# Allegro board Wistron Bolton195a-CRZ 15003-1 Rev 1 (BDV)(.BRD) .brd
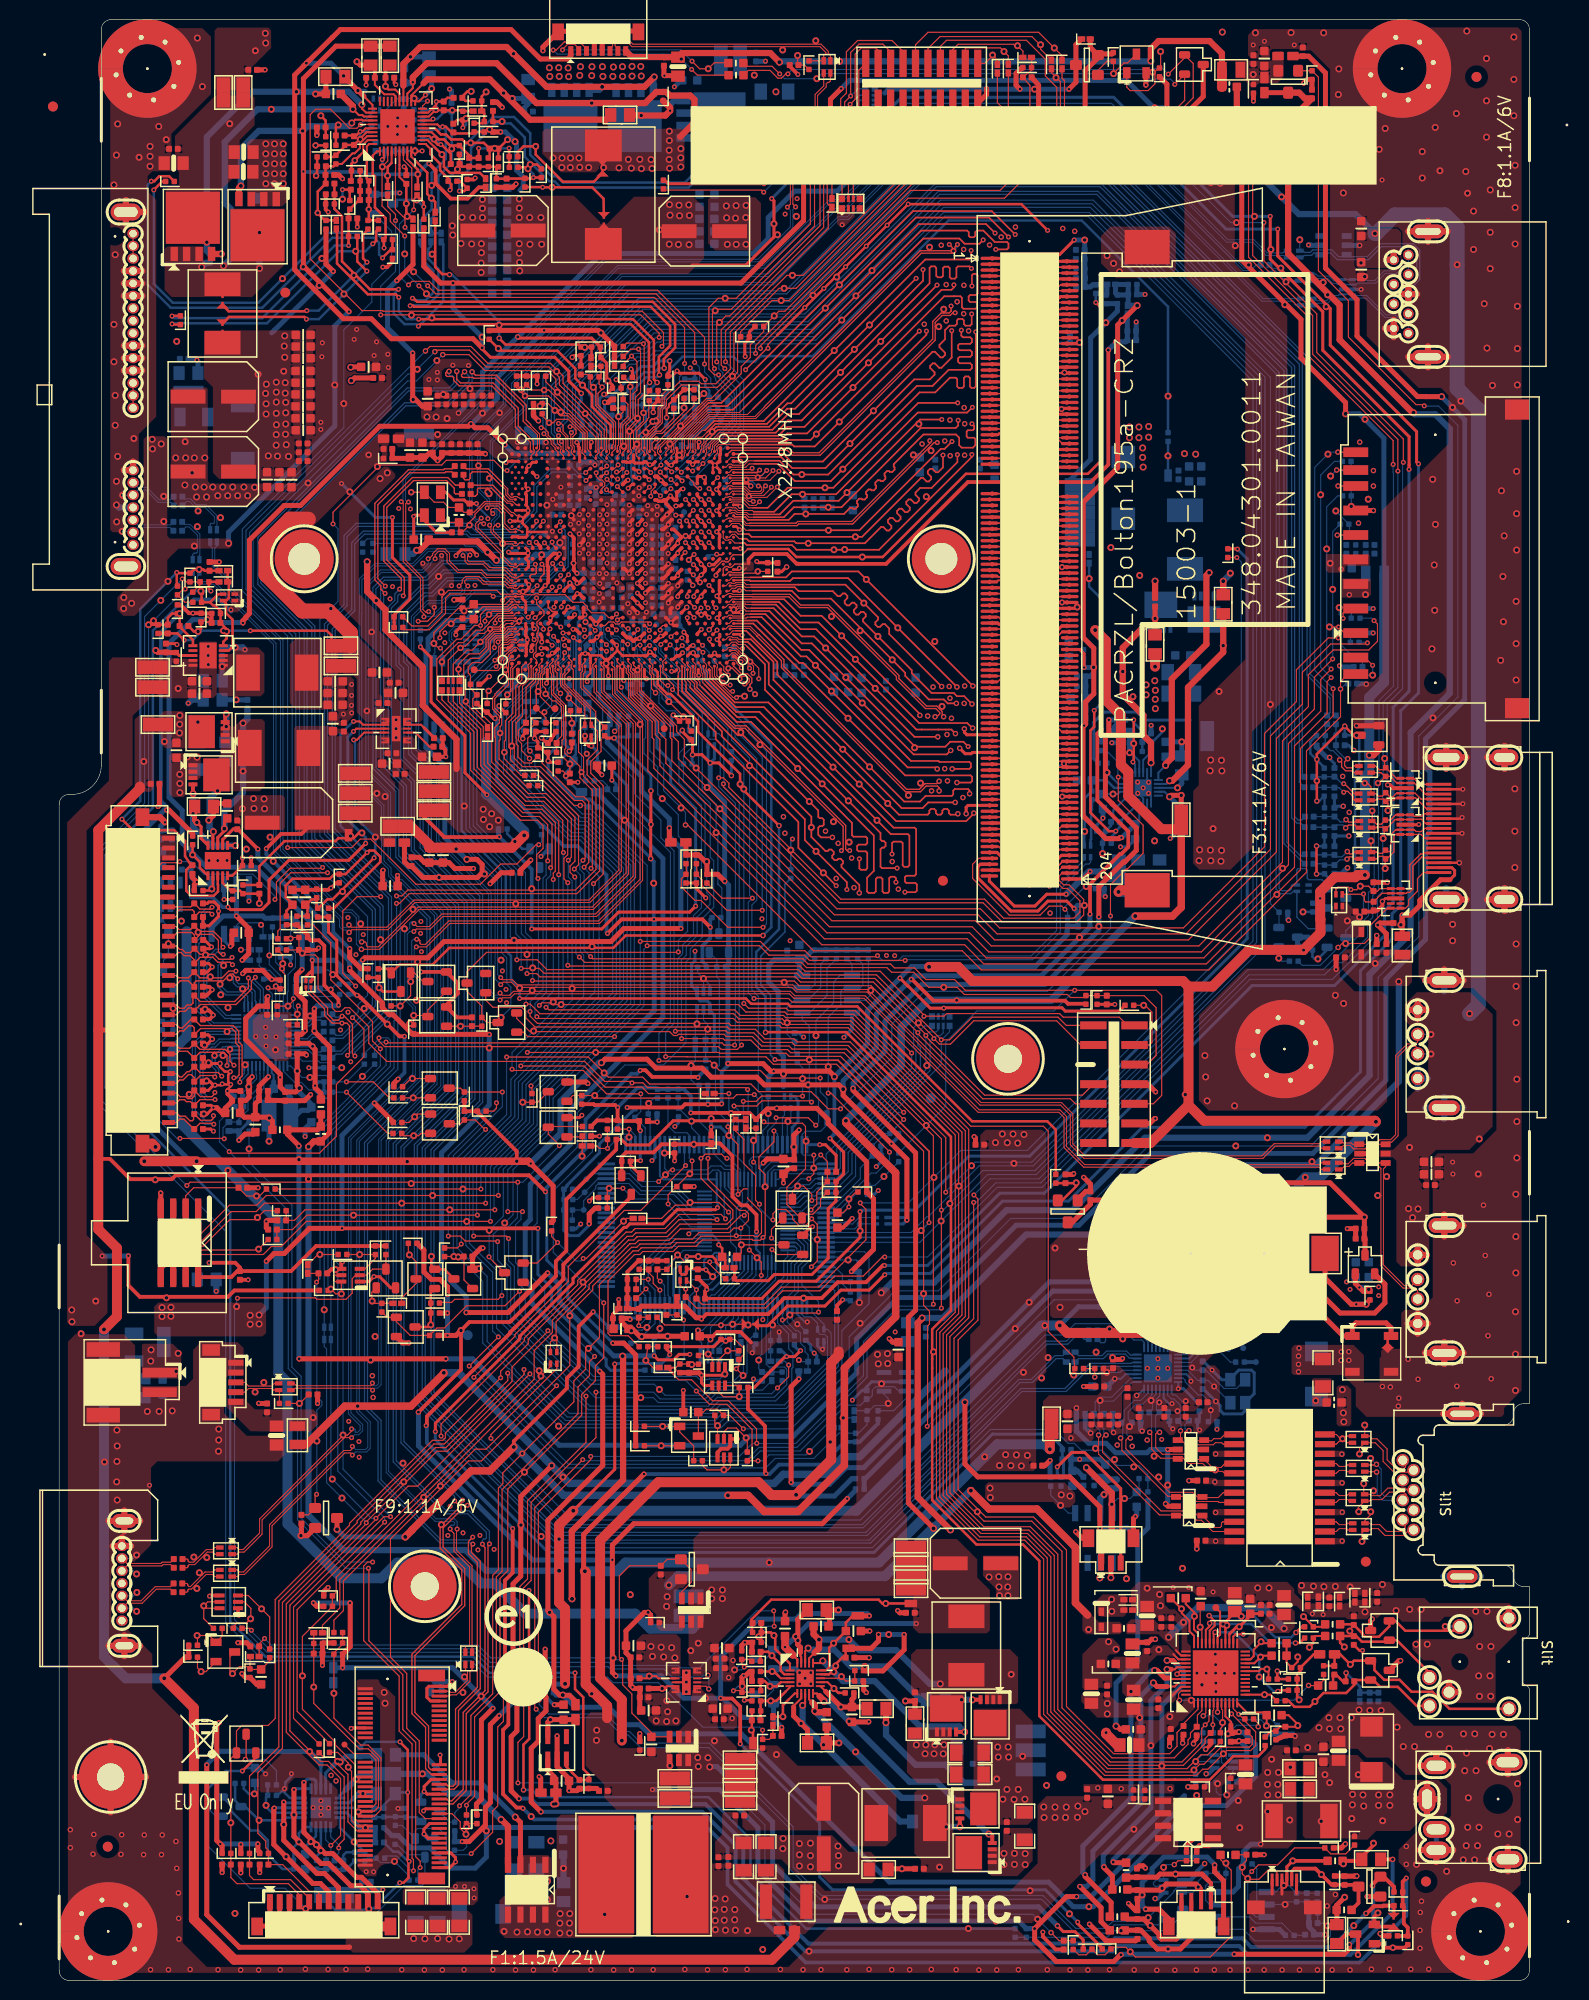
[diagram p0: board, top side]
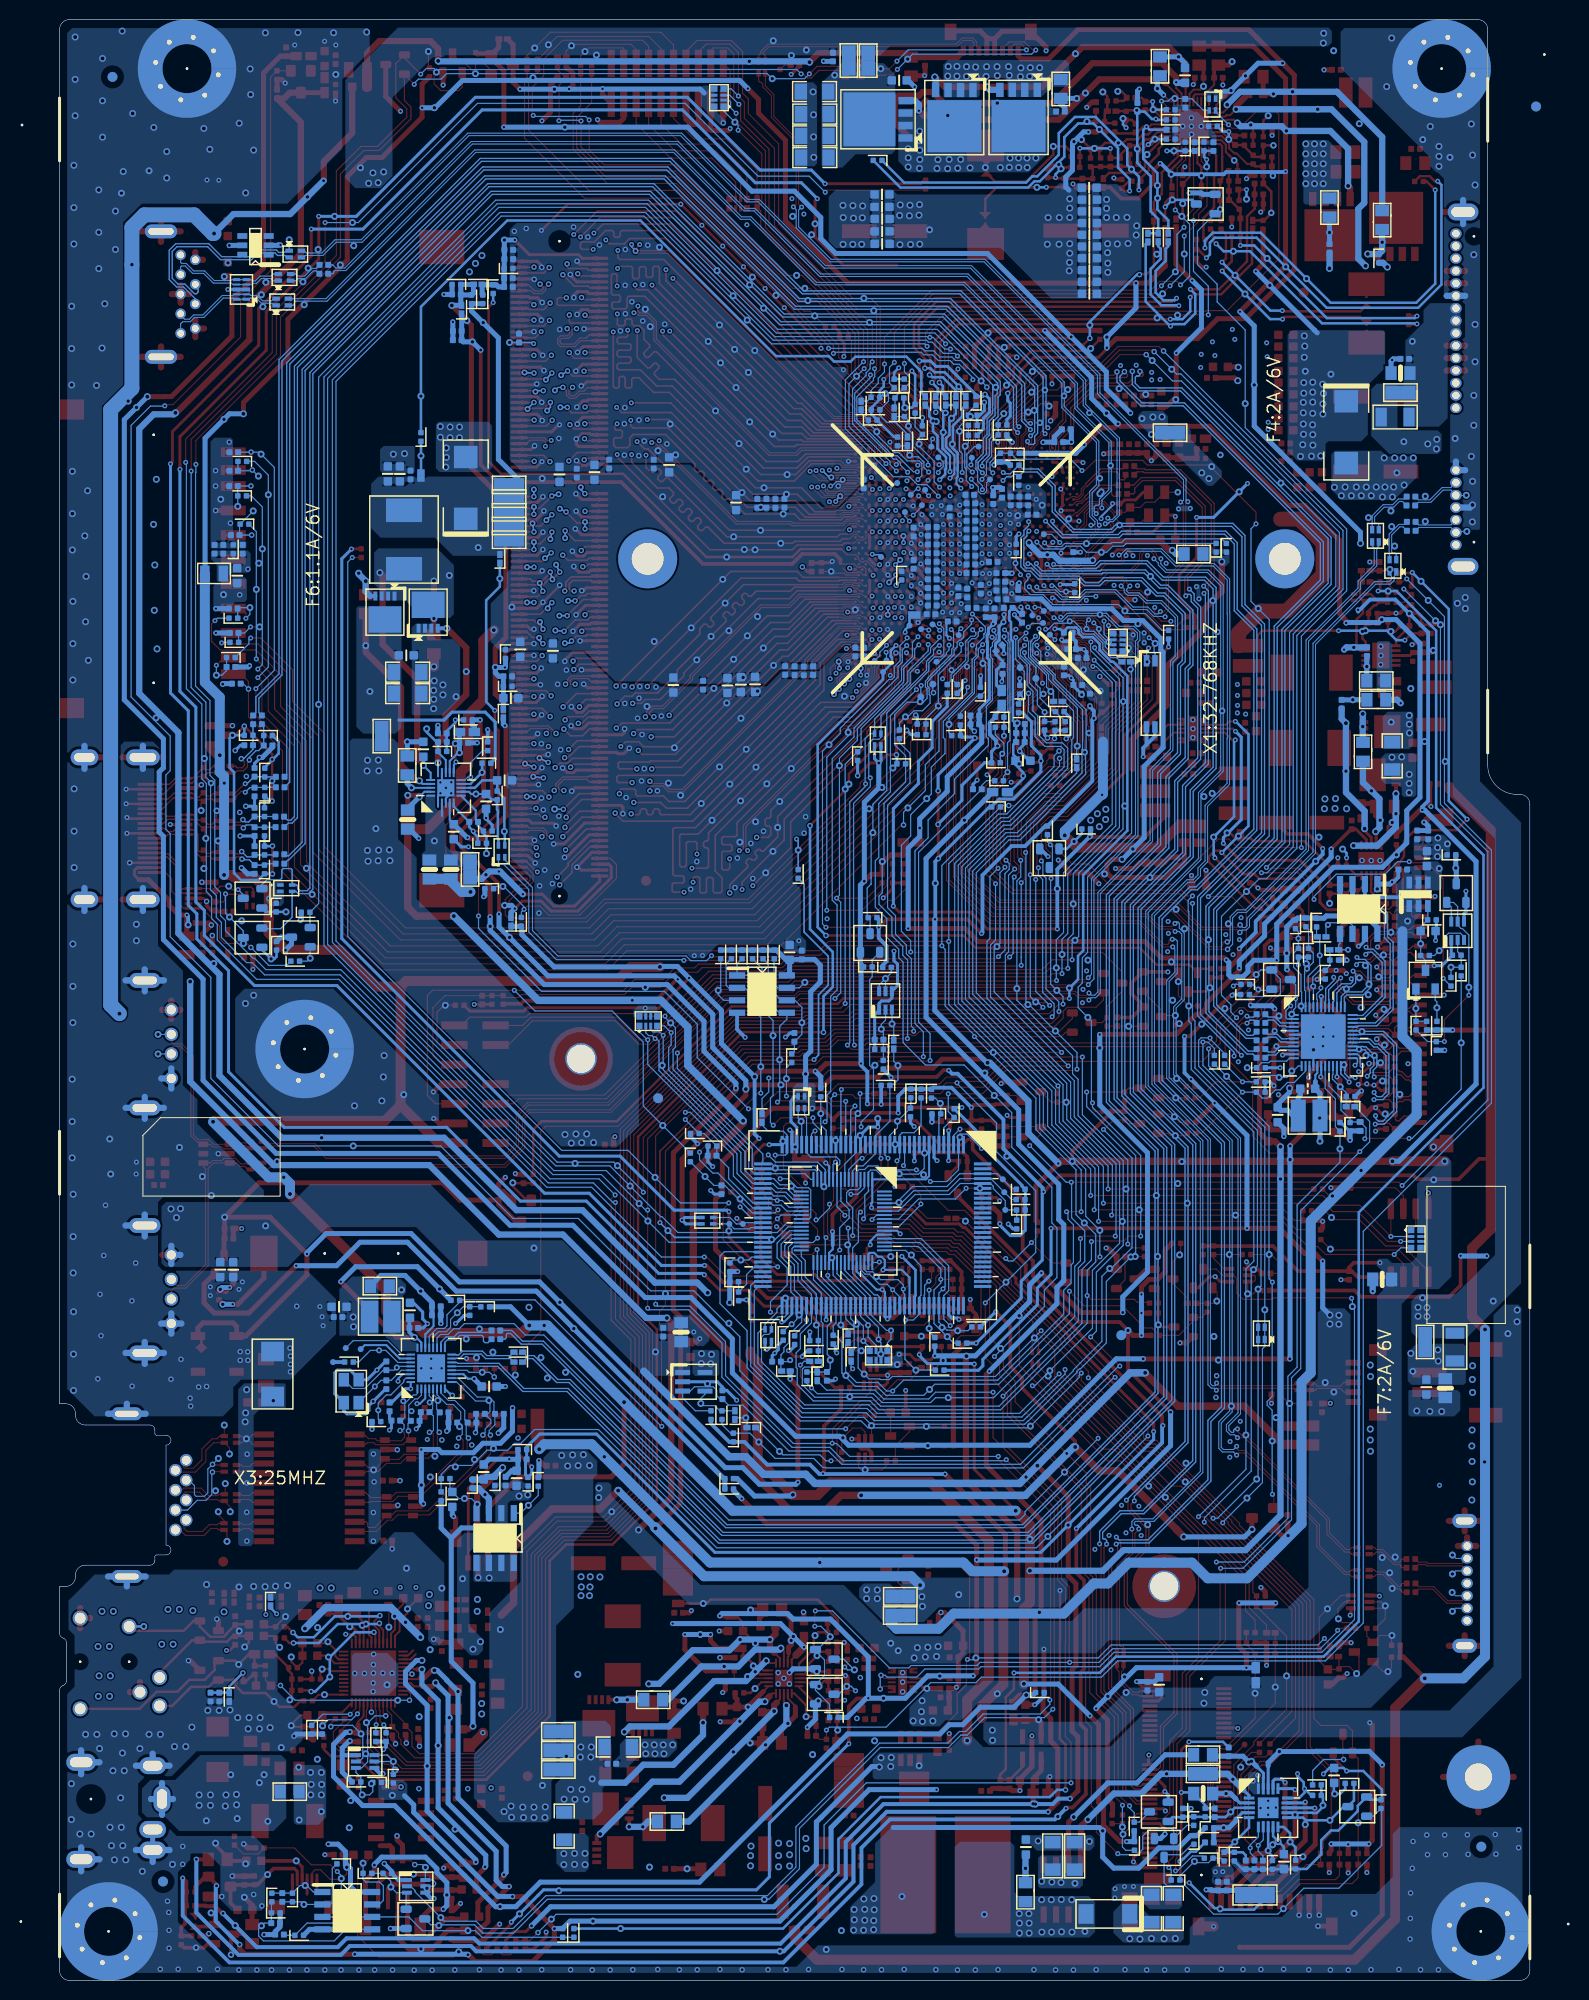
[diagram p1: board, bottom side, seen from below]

Outline 150 x 200 mm; copper layers: TOP, L2VCC, L3, BOTTOM. Coordinates in mm from the lower left corner of the outline.
Outline path: 0,119.97 0,1 arc(0.29,0.29) 1,0 149,0 arc(149.71,0.29) 150,1 150,29.6 arc(149.9,29.9) 149.65,30.08 arc(149.4,30.26) 149.3,30.55 149.3,34.45 arc(149.4,34.74) 149.65,34.92 arc(149.9,35.1) 150,35.4 150,40.18 149.38,40.18 arc(148.67,40.47) 148.38,41.18 148.38,41.35 arc(148.09,42.06) 147.38,42.35 140.78,42.35 arc(140.43,42.5) 140.28,42.85 140.28,43.2 arc(140.22,43.34) 140.08,43.4 139.14,43.4 arc(138.64,43.9) 139.14,44.4 139.14,54.6 arc(138.64,55.1) 139.14,55.6 140.08,55.6 arc(140.22,55.66) 140.28,55.8 140.28,56.15 arc(140.43,56.5) 140.78,56.65 147.38,56.65 arc(148.09,56.94) 148.38,57.65 148.38,57.82 arc(148.67,58.53) 149.38,58.82 150,58.82 150,199 arc(149.71,199.71) 149,200 5.3,200 arc(4.59,199.71) 4.3,199 4.3,123.97 arc(3.42,121.85) 1.3,120.97 1,120.97 arc(0.29,120.68) 0,119.97

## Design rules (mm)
constraint set DEFAULT: min track width 0.127, pair gap 0.102
net group C_GPP_TXN0: nets C_GPP_TXN0 PCIE_C_TXN0
net group C_GPP_TXN1: nets C_GPP_TXN1 PCIE_C_TXN1
net group C_GPP_TXP0: nets C_GPP_TXP0 PCIE_C_TXP0
net group C_GPP_TXP1: nets C_GPP_TXP1 PCIE_C_TXP1
net group CK_BLAN_DN: nets CK_BLAN_DN F_GPP_CLK0N
net group CK_BLAN_DP: nets CK_BLAN_DP F_GPP_CLK0P
net group DP0_AUXN: nets DP0_AUXN DP0_AUXN_PS8625
net group DP0_AUXP: nets DP0_AUXP DP0_AUXP_PS8625
net group DP0_TXN0: nets DP0_TXN0 M_DP0_TXN0
net group DP0_TXN1: nets DP0_TXN1 M_DP0_TXN1
net group DP0_TXP0: nets DP0_TXP0 M_DP0_TXP0
net group DP0_TXP1: nets DP0_TXP1 M_DP0_TXP1
net group DP1_TX: nets DP1_AUXN DP1_AUXP
net group F_USB0N: nets F_USB0N USB_PN0_C
net group F_USB0P: nets F_USB0P USB_PP0_C
net group F_USB1N: nets F_USB1N USB_PN1_2-
net group F_USB1P: nets F_USB1P USB_PP1_2+
net group F_USB2N: nets F_USB2N USB_PN2_11-
net group F_USB2P: nets F_USB2P USB_PP2_11+
net group F_USB4N: nets F_USB4N USB_PN4_C
net group F_USB4P: nets F_USB4P USB_PP4_C
net group F_USB5N: nets F_USB5N USB_PN5*
net group F_USB5P: nets F_USB5P USB_PP5*
net group HDMI_4: nets HDMI_HPDET_CN HDMI_HTPLG_CN1
net group MEM_MA_DQS0: nets MEM_MA_DQS_N0 MEM_MA_DQS_P0
net group MEM_MA_DQS1: nets MEM_MA_DQS_N1 MEM_MA_DQS_P1
net group MEM_MA_DQS2: nets MEM_MA_DQS_N2 MEM_MA_DQS_P2
net group MEM_MA_DQS3: nets MEM_MA_DQS_N3 MEM_MA_DQS_P3
net group MEM_MA_DQS4: nets MEM_MA_DQS_N4 MEM_MA_DQS_P4
net group MEM_MA_DQS5: nets MEM_MA_DQS_N5 MEM_MA_DQS_P5
net group MEM_MA_DQS6: nets MEM_MA_DQS_N6 MEM_MA_DQS_P6
net group MEM_MA_DQS7: nets MEM_MA_DQS_N7 MEM_MA_DQS_P7
net group OTHER_10_VIA_14: nets 12V_EN_G 12V_EN_G1
net group PCIE_C_RXN0: nets PCIE_C_RXN0 PCIE_RXN_LAN_C
net group PCIE_C_RXP0: nets PCIE_C_RXP0 PCIE_RXP_LAN_C
net group SATA_RXN1_C: nets SATA_RXN1_C SATA_RXN1_N
net group SATA_RXP1_C: nets SATA_RXP1_C SATA_RXP1_N
net group SATA_TXN1_C: nets SATA_TXN1_C SATA_TXN1_N
net group SATA_TXP1_C: nets SATA_TXP1_C SATA_TXP1_N
net group SCALAR_4: nets EDID_RDY RTL_ISOLATE_N
net group USB30_RN0_C: nets USB30_RN0_C USB30_RXN0
net group USB30_RP0_C: nets USB30_RP0_C USB30_RXP0
net group AMPGND_40: nets AMPGND
net group AUDIO_8_10: nets AUD_CBN AUD_CBP BZ_ON
net group AUDIO_12_10: nets AUD_VREF
net group AUDIO_AMP: nets F_HPO_L F_HPO_L_1 F_HPO_R F_HPO_R_1 FM_L_CODEC FM_R_CODEC HP_OUT_L_CON HP_OUT_R_CON JDREF_1 MIC2 MIC_IN_JACK MIC_VREFL MIC_VREFR PCH_SPKR1
net group AZALIA-MW: nets AZ_BCLK AZ_BCLK_M AZ_RST_N AZ_RST_N_M AZ_SDIN0 AZ_SDIN0_R AZ_SDIN1 AZ_SDIN2 AZ_SDIN3 AZ_SDOUT AZ_SDOUT_M AZ_SYNC AZ_SYNC_M
net group CR-DATA: nets SD_CD# SD_CLK SD_CMD SD_DATA0 SD_DATA1 SD_DATA2 SD_DATA3 SD_WP
net group DMIC_5.5-MW: nets DMIC_CLK DMIC_CLK_W DMIC_DATA DMIC_DATA_W
net group DP1_C_TXN0: nets DP1_C_TXN0 DP1_TXN0 DP1_TXN0_C
net group DP1_C_TXN1: nets DP1_C_TXN1 DP1_TXN1 DP1_TXN1_C
net group DP1_C_TXN2: nets DP1_C_TXN2 DP1_TXN2 DP1_TXN2_C
net group DP1_C_TXN3: nets DP1_C_TXN3 DP1_TXN3 DP1_TXN3_C
net group DP1_C_TXP0: nets DP1_C_TXP0 DP1_TXP0 DP1_TXP0_C
net group DP1_C_TXP1: nets DP1_C_TXP1 DP1_TXP1 DP1_TXP1_C
net group DP1_C_TXP2: nets DP1_C_TXP2 DP1_TXP2 DP1_TXP2_C
net group DP1_C_TXP3: nets DP1_C_TXP3 DP1_TXP3 DP1_TXP3_C
net group EDP_LVDS: nets EDP_LVDS_L0_N EDP_LVDS_L0_P EDP_LVDS_L1_N EDP_LVDS_L1_P EDP_LVDS_L2_N EDP_LVDS_L2_P EDP_LVDS_L3_N EDP_LVDS_L3_P EDP_LVDS_LC_N EDP_LVDS_LC_P EDP_LVDS_U0_N EDP_LVDS_U0_P EDP_LVDS_U1_N EDP_LVDS_U1_P EDP_LVDS_U2_N EDP_LVDS_U2_P EDP_LVDS_U3_N EDP_LVDS_U3_P EDP_LVDS_UC_N EDP_LVDS_UC_P
net group EUP_CTRL_4: nets EUP_EN EUP_R1 EUP_R2 EUP_R3 EUP_R4 EUP_R5 EUP_R6
net group FAN: nets CPU_FANCTL1 SIO_BLEN SIO_BLEN_SMI
net group HDA_4: nets AUD_LINK_RST_N1 COMBO JACK JD_HP_R PD PD#_C
net group HDA_4_COMBO: nets COMBO
net group HDT: nets APU_DBRDY APU_DBREQ APU_DBREQ# APU_TCK APU_TDI APU_TDO APU_TMS APU_TRST HDT_C_M1 HDT_C_M2 HDT_C_M3 HDT_PW_M3 HDT_PW_M4 HDT_RST0 HDT_RST1 HDT_TRST
net group INT_SPKR_20_20: nets SPKR_L+ SPKR_L- SPKR_OUT_L+_C SPKR_OUT_L-_C SPKR_OUT_R+_C SPKR_OUT_R-_C SPKR_R+ SPKR_R-
net group LAN_CTRL_4: nets LAN_CLKREQ_N LAN_EEDO LAN_EESK LAN_RSET
net group LCD_CTRL_4_VIA_14: nets LCD_5V_EN LCD_5V_EN1 LCD_5V_EN2 LCD_5V_EN3 LCD_5V_EN4 SCALAR_VDD_EN1
net group LED_15_10: nets LINK*_ACTIVITY_L PWRLED_CON SPEED_100*_L SUSLED_1 SUSLED_2 SUSLED_CON SUSLED_CON_P1 SUSLED_N SUSLED_R_N_1 SUSLED_R_N_PWM V_5_LED
net group LVDS-4: nets BKLT_ADJ BKLT_EN BKLT_EN_D DP0_HPD_G DP_BLON DP_DIGON DP_VARY_BL DP_VARY_BL_R PS8625_BKLT_EN PS8625_BKLT_PWM PS8625_LCD_PW_EN
net group MDI0+: nets MDI0+ MDI0+_C MDI0+_R
net group MDI0-: nets MDI0- MDI0-_C MDI0-_R
net group MDI1+: nets MDI1+ MDI1+_C MDI1+_R
net group MDI1-: nets MDI1- MDI1-_C MDI1-_R
net group MDI2+: nets MDI2+ MDI2+_C MDI2+_R
net group MDI2-: nets MDI2- MDI2-_C MDI2-_R
net group MDI3+: nets MDI3+ MDI3+_C MDI3+_R
net group MDI3-: nets MDI3- MDI3-_C MDI3-_R
net group MEM_DA_CHECK_DM-MW: nets MEM_MA_DM8
net group MEM_MA_CTL_CLK: nets MEM_MA0_CKE0 MEM_MA0_CKE1 MEM_MA0_CLK0_N MEM_MA0_CLK0_P MEM_MA0_CLK1_N MEM_MA0_CLK1_P MEM_MA0_CS_L0 MEM_MA0_CS_L1 MEM_MA0_ODT0 MEM_MA0_ODT1 MEM_MA_ADD0 MEM_MA_ADD1 MEM_MA_ADD2 MEM_MA_ADD3 MEM_MA_ADD4 MEM_MA_ADD5 MEM_MA_ADD6 MEM_MA_ADD7 MEM_MA_ADD8 MEM_MA_ADD9 MEM_MA_ADD10 MEM_MA_ADD11 MEM_MA_ADD12 MEM_MA_ADD13 MEM_MA_ADD14 MEM_MA_ADD15 MEM_MA_BANK0 MEM_MA_BANK1 MEM_MA_BANK2 MEM_MA_CAS# MEM_MA_RAS# MEM_MA_WE#
net group MEM_MA_DQ0: nets MEM_MA_DATA0 MEM_MA_DATA1 MEM_MA_DATA2 MEM_MA_DATA3 MEM_MA_DATA4 MEM_MA_DATA5 MEM_MA_DATA6 MEM_MA_DATA7 MEM_MA_DM0
net group MEM_MA_DQ1: nets MEM_MA_DATA8 MEM_MA_DATA9 MEM_MA_DATA10 MEM_MA_DATA11 MEM_MA_DATA12 MEM_MA_DATA13 MEM_MA_DATA14 MEM_MA_DATA15 MEM_MA_DM1
net group MEM_MA_DQ2: nets MEM_MA_DATA16 MEM_MA_DATA17 MEM_MA_DATA18 MEM_MA_DATA19 MEM_MA_DATA20 MEM_MA_DATA21 MEM_MA_DATA22 MEM_MA_DATA23 MEM_MA_DM2
net group MEM_MA_DQ3: nets MEM_MA_DATA24 MEM_MA_DATA25 MEM_MA_DATA26 MEM_MA_DATA27 MEM_MA_DATA28 MEM_MA_DATA29 MEM_MA_DATA30 MEM_MA_DATA31 MEM_MA_DM3
net group MEM_MA_DQ4: nets MEM_MA_DATA32 MEM_MA_DATA33 MEM_MA_DATA34 MEM_MA_DATA35 MEM_MA_DATA36 MEM_MA_DATA37 MEM_MA_DATA38 MEM_MA_DATA39 MEM_MA_DM4
net group MEM_MA_DQ5: nets MEM_MA_DATA40 MEM_MA_DATA41 MEM_MA_DATA42 MEM_MA_DATA43 MEM_MA_DATA44 MEM_MA_DATA45 MEM_MA_DATA46 MEM_MA_DATA47 MEM_MA_DM5
net group MEM_MA_DQ6: nets MEM_MA_DATA48 MEM_MA_DATA49 MEM_MA_DATA50 MEM_MA_DATA51 MEM_MA_DATA52 MEM_MA_DATA53 MEM_MA_DATA54 MEM_MA_DATA55 MEM_MA_DM6
net group MEM_MA_DQ7: nets MEM_MA_DATA56 MEM_MA_DATA57 MEM_MA_DATA58 MEM_MA_DATA59 MEM_MA_DATA60 MEM_MA_DATA61 MEM_MA_DATA62 MEM_MA_DATA63 MEM_MA_DM7
net group MEM_MISC-MW: nets MEM_MA_EVENT_L MEM_MA_RESET# SIO_MEM_EVENT_L
net group OCP_6: nets ADP_OCP OCP_0 OCP_1 OCP_2 OCP_3 OCP_6 OCP_7 OCP_8
net group OTHER_4: nets 1D5V_S3_PG 1D5V_S3_PG_R A_RST_N APU_BLEN_SMI APU_PROCHOT# APU_PROCHOT#_R APU_PWRGD APU_PWRGD_BUF APU_SIC APU_SID APU_SVC APU_SVD APU_SVT AUD_CPVEE BLANCLK_REQ_N BLINK BT_DISABLE_N# BUFFER1_M4 BYPASSCLK_H BYPASSCLK_L DAC_ZVSS DIMM1_SA0 DP0_HPD_N DP0_HPD_NR DP1_HPD_N DP_2K_ZVSS DP_150_ZVSS DP_REXT EC_SMI# EC_SMI#_APU EUP_DSW_SEL FP_RST_N HDMI_EN ICH_RSMRST_N_R ITE_DEB KA20GATE KA20GATE_SIO KBRST_N LAD0_FWH0 LAD1_FWH1 LAD2_FWH2 LAD3_FWH3 LAN_WAKE LDT_PWRGD_R LDT_RST LDT_RST#_BUF LDT_RST#_R LFRAMEJ_FW4 LPC_CLK0_R LPC_CLK1 LPC_CLK1_R LPC_PME_N LPC_SIO_CLK0 MEM_ZVDDIO MODE_CFG0 MODE_CFG1 NGFF_SUSCLK P_RX_ZVDD P_TX_ZVDD PB_IN_N_1 PCIE_RST_N PCIE_RST_N_R PCIE_WAKE_N_PCIE PCIRST2# PLT_WLAN_RST PLT_WLAN_RST# PLTRST_LAN PME#_M PWRBTN# PWRBTN#_1 PWRBTN_IN PWRGD_3V_LL PWRGD_PS_L PWRGD_PS_L1 PWRGD_PS_L2 RSMRST*_R RSMRST_N RSMRST_N_FCH SERIRQ_N SIO_PWNBTN_N SLP_S3_N SLP_S5_N SLP_S5_N_R SPI_SW SVC_VDD SVD_VDD SVT_VDD SW_ON_N_SIO SYS_ID2 SYS_ID3 SYS_PWRGD TEST18_M TEST19_M TEST_MODE THERMAL_SHUT# THERMAL_SHUT#_SIO USB_COMP_M USB_OC_01 USB_OC_02 USB_OC_03 USB_OC_23 USBSS_CALRN USBSS_CALRP V_3P3_DBP VRM_PWRGD VSS_BEEMA WLAN_CLKREQ WLAN_CLKREQ_CPU#
net group OTHER_4_VIA_14: nets SYS_PWRGD_HV SYS_PWRGD_HV_1 SYS_PWRGD_HV_2
net group OTHER_10: nets ADU_LDO_CAP APU_ALERT# HDMI_Q76_M Q5102_GATE Q5103_GATE SPKR
net group OTHER_40: nets CPU_FANTACH1 FAN5V_OUT FAN5V_OUT_CONN
net group POWER_4.5: nets PWR_ID0 PWR_ID1 PWR_ID2
net group POWER_10: nets 0D95V_S0_EN 1D8V_S0_EN APU_VDDIO_AZ M_VREFDQ SENSE_A SIO_MAIN_VCC3 SIO_VREF VCORE_PWROK
net group POWER_10_10: nets 0D95V_S5_PG 0P95V_MAIN_APU_M 1P8V_PWR_PG +1P5V_LPS_APU PWR_1D8V_EN PWR_1D8V_FB PWR_1D8V_FB_A PWR_3D3V_ENTRIP1_D PWR_3D3V_ENTRIP2 PWR_3D3V_ENTRIP2_D PWR_3D3V_FB PWR_3D3V_FB_A PWR_3D3V_LDO3 PWR_5V3V_EMN PWR_5V3V_ENLDO PWR_5V3V_LDO5 PWR_5V3V_PGOOD PWR_5V3V_TON PWR_5V_ENTRIP1 PWR_5V_FB PWR_5V_FB_A PWR_CORE_PH1N PWR_CORE_PH1P PWR_CPU_COMP PWR_CPU_COMP_A PWR_CPU_COMPNB PWR_CPU_COMPNB_A PWR_CPU_EN PWR_CPU_FB PWR_CPU_FB_A PWR_CPU_FB_B PWR_CPU_FB_C PWR_CPU_FBNB PWR_CPU_FBNB_A PWR_CPU_FBNB_B PWR_CPU_IMON PWR_CPU_ISEN1 PWR_CPU_ISEN2 PWR_CPU_ISUMN PWR_CPU_ISUMN_A PWR_CPU_ISUMNNB PWR_CPU_ISUMNNB_B PWR_CPU_ISUMP_A PWR_CPU_NB_IMON PWR_CPU_NB_NTC PWR_CPU_NB_NTCA PWR_CPU_NTC PWR_CPU_NTC_A PWR_CPU_PWROK PWR_CPU_RTN PWR_CPU_VDDIO PWR_CPU_VR_HOT PWR_CPU_VSEN PWR_CPU_VSENNB PWR_V1P5A_EN PWR_VDDNB_ISUMP_A PWR_VDDNB_PH_N PWR_VDDNB_PH_P PWR_VDDP_CS PWR_VDDP_EN PWR_VDDP_FB PWR_VDDP_FB_A PWR_VDDP_RF PWR_VDDQ_CS PWR_VDDQ_EN PWR_VDDQ_FB PWR_VDDQ_SENSE PWR_VDDQ_TON PWR_VDDQ_VDD PWR_VDDQ_VTT_EN V_VCORE_EN VBAT_SB_N VDD_095_FB_H_CTL VDDCR_CPU_SENSE VDDCR_NB_SENSE VDDIO_SUS_FB_H VDDIO_SUS_FB_R VDDIO_SUS_SENSE VSS_SENSE
net group POWER_10_10_VIA_14: nets ISET LPF OZ554_EMA OZ554_PWM RT SSTCMP SSTCMP_1 STATUS
net group POWER_20: nets 1D5V_S5 3D3V_2136 3D3V_S5_RSV +3VM +RTCVCC APU_M_VREFDQ_SUS APU_VDD33_ALW APU_VDD_33 BATTERY D2_M D2_M1 DDR_VREF_S3 MEM_VREFCA_SUS P_1.2V_EDP P_3.3V_EDP_VDDIO P_3.3V_EDP_VDDIOX PS8625_SW PWR_1D8V_SVIN PWR_5V3V_VIN PWR_V1P5A PWR_V1P5A_VIN SIO_VCORE VTT_CT_0.95V VTT_CT_1.8V VTT_CT_3.3V VTT_CT_5VC
net group POWER_20_20_VIA_14: nets ISEN1 ISEN2 ISEN3 ISEN4 ISW OZ554_VIN PWR_1D8V_SNB PWR_3D3V_BOOT PWR_3D3V_BOOT_A PWR_3D3V_SNB PWR_5V_BOOT PWR_5V_BOOT_A PWR_5V_SNB PWR_CORE_BOOT1 PWR_CORE_BOOT1_A PWR_CORE_SNB PWR_VDDNB_BOOT PWR_VDDNB_BOOT_A PWR_VDDNB_SNB PWR_VDDP_BOOT PWR_VDDP_BOOT_A PWR_VDDP_SNB PWR_VDDQ_BOOT PWR_VDDQ_BOOT_A PWR_VDDQ_SNB VREF
net group POWER_20_VIA_14: nets V_5_SUS1
net group POWER_25_20_VIA_14: nets LDR LDR_1 PWR_3D3V_HG PWR_3D3V_HG_A PWR_3D3V_LG PWR_5V_HG PWR_5V_HG_A PWR_5V_LG PWR_CORE_HG1 PWR_CORE_HG1_A PWR_CORE_LG1 PWR_VDDNB_HG PWR_VDDNB_HG_A PWR_VDDNB_LG PWR_VDDP_HG PWR_VDDP_HG_A PWR_VDDP_LG PWR_VDDQ_HG PWR_VDDQ_HG_A PWR_VDDQ_LG SNB
net group POWER_40: nets 1D5V_S0 +3VL +5VL PWR_VDDQ_VDDP PWR_VDDQ_VTTIN SIO_AGND SIO_AVCC3
net group POWER_40_VIA_14: nets 5V_S5_LCD_DOWN +5VLCDDDC V_5_PWR1
net group POWER_60: nets 0D75V_S0 PWR_CPU_VDD PWR_CPU_VDDP
net group PS8625: nets PS8625_HPD
net group PWRGD_4_10: nets 3V_5V_POK APU_VRM_PWRGD PWRGD_3V_B_1 PWROK3_1 PWROK3_1_R PWROK3_2 PWROK3_2_R S0_PWR_GOOD SIO_ATXPG V12 V33
net group RUNPWR_4_VIA_14: nets 12V_EN_D RUN_EN RUNPWR_G RUNPWR_R3 RUNPWR_R4 RUNPWR_R5 RUNPWR_R6
net group SATA_RX0N: nets SATA_RX0N SATA_RXN0_C SATA_RXN0_N
net group SATA_RX0P: nets SATA_RX0P SATA_RXP0_C SATA_RXP0_N
net group SATA_TX0N: nets SATA_TX0N SATA_TXN0_C SATA_TXN0_N
net group SATA_TX0P: nets SATA_TX0P SATA_TXP0_C SATA_TXP0_N
net group SD_DATA-MS: nets SD_CLK_CH SD_CMD_CH SD_DATA0_CH_C SD_DATA1_CH_C SD_DATA2_CH_C SD_DATA3_CH_C SD_PWRCTL_CH
net group SIO_4: nets 5V_FANCTL1_FSM# BT_DISABLE_N CPU_FANCTL1_5V DIMM_TMPIN2 EC_EUP EC_EUP_EN EC_EUP_EN# HM_VCCP HM_VCCP_R KBCLK KDAT LDRQ# MCLK MDAT PCIRST1# PLTRST*_SIO REMOTE1+ SIO_3VSB SIO_AMD SVID_EN SIO_BOARD_ID1 SIO_BOARD_ID2 SIO_BOARD_ID3 SIO_CE_N SIO_CLK_DB SIO_COPEN# SIO_DAT_DB SIO_DEBUG_RX SIO_DEBUG_TX SIO_GP31 SIO_GP45 SIO_JP2 SIO_K8PWR_EN SIO_PCIRSTIN# SIO_PSON_N SIO_PSON_N_D SIO_VIN1 SIO_VIN2 SIO_VIN3 SIO_VIN4 SIO_VIN5 SIO_WRST# SYS_3VSB VBAT_SIO WIFI_DISABLE_N
net group SMBUS: nets M1_SMB_CLK M1_SMB_DATA PS8625_INI_SCL PS8625_INI_SCL_R PS8625_INI_SDA PS8625_INI_SDA_R PS8625_ROM2_CLK PS8625_ROM2_DAT SIO_SMCLK0 SIO_SMCLK0_1 SIO_SMCLK0_2 SIO_SMDAT0 SIO_SMDAT0_1 SIO_SMDAT0_2 SMB0_CLK SMB0_DATA SMB1_CLK SMB1_DATA
net group SPI: nets ROM_RST# SIO_HOLD# SIO_SCK SIO_SCK_R SIO_SI SIO_SO SIO_WP# SPI_CLK SPI_CLK_R SPI_CS0_N SPI_DATAIN SPI_DATAOUT SPI_SI_R SPI_SO SPI_WP# SPI_WP#_R SPI_WP_R_N SST_HOLDJ_1 SST_HOLDJ_1_R
net group TESTPOINT: nets APU_TEST0 APU_TEST1 APU_TEST2 APU_TEST4_THERMDA APU_TEST5_THERMDC APU_TEST6_DIRECRACKMON APU_TEST14_BP0 APU_TEST15_BP1 APU_TEST16_BP2 APU_TEST17_BP3 APU_TEST28_PLLCHARZ_H APU_TEST28_PLLCHARZ_L APU_TEST31_M_TEST APU_TEST36_FREE_2 APU_TEST37_FREE_2 LDRQ0# M_ANALOGIN M_ANALOGOUT TMON_CAL TP20 TP29 TP48 TP49 TP51 TP52 TP53 TP_LPC_CLKRUN# TP_LPC_PD# USB_ATEST0 USB_ATEST1
net group USB30_TN0R*: nets USB30_TN0_C USB30_TN0R* USB30_TXN0
net group USB30_TP0R*: nets USB30_TP0_C USB30_TP0R* USB30_TXP0
net group USB_CTRL_4: nets F_USB1N_RC F_USB2N_RC USB30_EN USB_EN USB_EN1 USB_EN2 USB_EN3 USB_EN4 USB_EN5 USB_EN6 USB_PWR_EUP
net group USB_POWER_40: nets VCC5_CAM
net group VGA_RGB: nets VGA_FCH_DDCSCL VGA_FCH_DDCSDA VGA_HSYNC_3V VGA_VSYNC_3V
net group XTAL: nets CLK_48M_SIO LAN_XTAL1 LAN_XTAL2 PCH_CLK48 PCH_CLK48_F RTC_CLK X32K_X1 X32K_X2 X48M_X1 X48M_X2

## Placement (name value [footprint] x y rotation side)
AUDIO1  ALC269Q-VC3-GRT-GP  [QFN48J6-G465H40]  117.98 31.34 180 top
AUDS1  AUDIO-JK540-GP  [HTJ-035-24FBSPT]  147.9 32.5 270 top
BTT1  BAT-AAA-BAT-034-K01-A-GP  [AAA-BAT-034-K01]  122.95 74.15 0 top
C1  SCD1U16V2KX-3GP  [C402H22]  109.51 171.97 270 bottom
C2  SCD1U16V2KX-3GP  [C402H22]  109.42 168.23 270 bottom
C3  SC1KP50V2KX-1GP  [C402H22]  109.43 167.3 270 bottom
C4  SCD1U16V2KX-3GP  [C402H22]  41.53 152.51 270 top
C5  SCD1U16V2KX-3GP  [C402H22]  41.53 151.62 270 top
C6  SCD1U16V2KX-3GP  [C402H22]  40.8 154.46 270 top
C7  SCD1U16V2KX-3GP  [C402H22]  40.8 153.57 270 top
C18  SCD1U16V2KX-3GP  [C402H22]  27.43 96.77 270 bottom
C19  SCD1U16V2KX-3GP  [C402H22]  27.43 95.89 270 bottom
C20  SCD1U16V2KX-3GP  [C402H22]  27.43 95 270 bottom
C21  SCD1U16V2KX-3GP  [C402H22]  27.43 94.11 270 bottom
C22  SC150P50V2KX-GP  [C402H22]  56.52 160.82 0 top
C23  SC150P50V2KX-GP  [C402H22]  53.22 164.25 0 top
C24  SCD1U16V2KX-3GP  [C402H22]  47.63 127.82 0 top
C25  SC150P50V2KX-GP  [C402H22]  52.3 126.7 180 top
C26  SCD01U25V2KX-3GP  [C402H22]  82.47 80.64 180 bottom
C27  SC150P50V2KX-GP  [C402H22]  78.82 82.47 270 top
C28  SCD01U25V2KX-3GP  [C402H22]  121.23 24.87 0 top
C29  SCD01U25V2KX-3GP  [C402H22]  50.3 126.22 270 top
C30  SC15P50V2JN-2-GP  [C402H22]  41.15 140.4 180 top
C31  SC15P50V2JN-2-GP  [C402H22]  41.15 138.48 0 top
C32  SCD01U16V2KX-3GP  [C402H22]  42.1 97.78 180 top
C33  SC100P50V2JN-3GP  [C402H22]  56.36 121.5 90 bottom
C34  SC100P50V2JN-3GP  [C402H22]  83.42 84.12 270 bottom
C35  SC100P50V2JN-3GP  [C402H22]  106.88 100 0 top
C36  SC22P50V2JN-4GP  [C402H22]  41.88 150.19 180 top
C37  SC22P50V2JN-4GP  [C402H22]  40.51 147.7 270 top
C38  SC10U6D3V3MX-GP  [C603H38]  66.08 178.4 270 bottom
C39  SC10U6D3V3MX-GP  [C603H38]  66.08 179.67 270 bottom
C40  SC10U6D3V3MX-GP  [C603H38]  66.08 177.13 270 bottom
C41  SC1U10V2KX-1GP  [C402H22]  60.96 148.24 270 bottom
C42  SC1U10V2KX-1GP  [C402H22]  60.96 147.36 270 bottom
C43  SC1U10V2KX-1GP  [C402H22]  60.96 146.47 270 bottom
C44  SC1U10V2KX-1GP  [C402H22]  60.96 145.58 270 bottom
C45  SC1U10V2KX-1GP  [C402H22]  60.96 144.69 270 bottom
C46  SC1U10V2KX-1GP  [C402H22]  60.96 142.91 270 bottom
C47  SC1U10V2KX-1GP  [C402H22]  57.03 150.66 90 bottom
C48  SC1U10V2KX-1GP  [C402H22]  57.03 146.21 90 bottom
C49  SC1U10V2KX-1GP  [C402H22]  57.14 151.53 90 bottom
C50  SC1U10V2KX-1GP  [C402H22]  57.03 144.43 90 bottom
C51  SC1U10V2KX-1GP  [C402H22]  57.03 145.32 90 bottom
C52  SCD1U16V2KX-3GP  [C402H22]  57.03 149.77 90 bottom
C53  SCD1U16V2KX-3GP  [C402H22]  57.03 148.88 90 bottom
C54  SCD1U16V2KX-3GP  [C402H22]  57.03 147.99 90 bottom
C55  SCD1U16V2KX-3GP  [C402H22]  57.03 147.1 90 bottom
C56  SCD1U16V2KX-3GP  [C402H22]  59.18 149.77 180 bottom
C57  SC180P50V2JN-1GP  [C402H22]  60.96 143.8 270 bottom
C58  SC10U6D3V3MX-GP  [C603H38]  37.59 161.33 180 top
C59  SC180P50V2JN-1GP  [C402H22]  48.06 156.9 270 bottom
C60  SC1U10V2KX-1GP  [C402H22]  44.07 161.2 180 top
C61  SC1U10V2KX-1GP  [C402H22]  43.18 161.2 180 top
C62  SC1U10V2KX-1GP  [C402H22]  42.17 161.2 180 top
C63  SC1U10V2KX-1GP  [C402H22]  41.28 161.2 180 top
C64  SC1U10V2KX-1GP  [C402H22]  40.39 161.2 180 top
C65  SC1U10V2KX-1GP  [C402H22]  38.61 161.2 180 top
C66  SC1U10V2KX-1GP  [C402H22]  39.5 161.2 180 top
C67  SC10U6D3V3MX-GP  [C603H38]  31.57 164.57 90 top
C68  SC10U6D3V3MX-GP  [C603H38]  23.71 153.07 0 top
C69  SC10U6D3V3MX-GP  [C603H38]  21.21 153.08 0 top
C70  SC10U6D3V3MX-GP  [C603H38]  22.47 153.06 0 top
C71  SC180P50V2JN-1GP  [C402H22]  53.98 143.55 90 bottom
C72  SC1U10V2KX-1GP  [C402H22]  54.74 151.04 0 bottom
C73  SC1U10V2KX-1GP  [C402H22]  53.85 151.67 0 bottom
C74  SC1U10V2KX-1GP  [C402H22]  56.01 141.89 180 bottom
C75  SC1U10V2KX-1GP  [C402H22]  54.74 144.69 270 bottom
C76  SC1U10V2KX-1GP  [C402H22]  51.18 150.91 0 bottom
C77  SC1U10V2KX-1GP  [C402H22]  52.07 150.91 0 bottom
C78  SC1U10V2KX-1GP  [C402H22]  57.03 143.55 270 bottom
C79  SC1U10V2KX-1GP  [C402H22]  52.96 150.91 0 bottom
C80  SC1U10V2KX-1GP  [C402H22]  24.9 154.97 90 top
C81  SC180P50V2JN-1GP  [C402H22]  33.54 156.21 90 top
C82  SC4D7U6D3V3MX-2GP  [C603H36]  37.06 156.09 0 top
C83  SC1U10V2KX-1GP  [C402H22]  42.67 156.25 0 top
C84  SC1U10V2KX-1GP  [C402H22]  41.79 156.25 0 top
C85  SC1U10V2KX-1GP  [C402H22]  40.9 156.25 0 top
C86  SC1U10V2KX-1GP  [C402H22]  40.01 156.25 0 top
C87  SC1U10V2KX-1GP  [C402H22]  38.1 156.27 0 top
C88  SC4D7U6D3V3KX-GP  [C603H36]  35.79 156.09 0 top
C89  SC180P50V2JN-1GP  [C402H22]  39.07 156.26 0 top
C90  SCD1U16V2KX-3GP  [C402H22]  50.77 149.5 90 bottom
C91  SCD1U16V2KX-3GP  [C402H22]  24.89 156.77 90 top
C92  SCD1U16V2KX-3GP  [C402H22]  24.9 155.86 90 top
C93  SCD1U16V2KX-3GP  [C402H22]  32.49 163.45 90 top
C94  SCD1U16V2KX-3GP  [C402H22]  77.89 150.66 0 bottom
C95  SCD1U16V2KX-3GP  [C402H22]  75.01 133.59 180 bottom
C96  SCD1U16V2KX-3GP  [C402H22]  67.92 135.49 180 bottom
C97  SCD1U16V2KX-3GP  [C402H22]  75.97 133.61 180 bottom
C98  SCD1U16V2KX-3GP  [C402H22]  78.82 150.66 0 bottom
C99  SCD1U16V2KX-3GP  [C402H22]  68.81 135.49 180 bottom
C100  SCD1U16V2KX-3GP  [C402H22]  62.87 147.74 0 bottom
C101  SCD1U16V2KX-3GP  [C402H22]  62.87 144.43 180 bottom
C102  SC180P50V2JN-1GP  [C402H22]  97.23 153.75 0 bottom
C103  SC180P50V2JN-1GP  [C402H22]  67.97 152.64 0 bottom
C104  SC180P50V2JN-1GP  [C402H22]  76.97 150.65 0 bottom
C105  SC180P50V2JN-1GP  [C402H22]  74.07 133.57 180 bottom
C106  SC4D7U6D3V3KX-GP  [C603H36]  51.71 124.41 90 bottom
C107  SC1U10V2KX-1GP  [C402H22]  51.97 128.15 90 bottom
C108  SC180P50V2JN-1GP  [C402H22]  53.22 139.99 270 bottom
C109  SC1U10V2KX-1GP  [C402H22]  51.98 126.32 90 bottom
C110  SC1U10V2KX-1GP  [C402H22]  51.97 127.24 90 bottom
C111  SC180P50V2JN-1GP  [C402H22]  54.62 139.49 0 bottom
C112  SC1U10V2KX-1GP  [C402H22]  55.51 139.49 0 bottom
C113  SC1U10V2KX-1GP  [C402H22]  56.62 128.13 270 bottom
C114  SC10U6D3V3MX-GP  [C603H38]  80.98 150.73 0 bottom
C115  SC10U6D3V3MX-GP  [C603H38]  80.49 132.17 180 bottom
C116  SC10U6D3V3MX-GP  [C603H38]  79.05 132.19 180 bottom
C117  SC180P50V2JN-1GP  [C402H22]  51.81 138.94 180 bottom
C118  SC180P50V2JN-1GP  [C402H22]  53.8 133.72 180 bottom
C119  SC180P50V2JN-1GP  [C402H22]  47.53 133.56 180 bottom
C120  SC180P50V2JN-1GP  [C402H22]  47.29 158.22 270 bottom
C121  SC180P50V2JN-1GP  [C402H22]  56.62 129.02 270 bottom
C122  SC180P50V2JN-1GP  [C402H22]  60.96 141.13 270 bottom
C123  SC180P50V2JN-1GP  [C402H22]  35.95 114.11 180 top
C124  SC1U10V2KX-1GP  [C402H22]  46.58 145.24 0 bottom
C125  SC10U6D3V3MX-GP  [C603H38]  36.93 146.96 270 top
C126  SC1U10V2KX-1GP  [C402H22]  60.96 140.24 270 bottom
C127  SC1U10V2KX-1GP  [C402H22]  58.3 141.64 0 bottom
C128  SC1U10V2KX-1GP  [C402H22]  58.93 138.62 270 bottom
C129  SC1U10V2KX-1GP  [C402H22]  57.41 141.51 0 bottom
C130  SC1U10V2KX-1GP  [C402H22]  61.09 139.35 270 bottom
C131  SC1U10V2KX-1GP  [C402H22]  56.9 139.99 90 bottom
C132  SC10U6D3V3MX-GP  [C603H38]  55.62 123.91 90 top
C133  SC10U6D3V3MX-GP  [C603H38]  33.76 111.63 270 top
C134  SC180P50V2JN-1GP  [C402H22]  60.96 142.02 270 bottom
C135  SCD22U6D3V2KX-1GP  [C402H22]  47.09 137.46 90 bottom
C136  SC1U6D3V2KX-GP  [C402H22]  102.67 81.76 180 top
C137  SC10U6D3V3MX-GP  [C603H38]  37.76 114.77 0 top
C138  SC10U6D3V3MX-GP  [C603H38]  39.15 114.77 0 top
C139  SC1U10V2KX-1GP  [C402H22]  46.12 132.13 270 bottom
C140  SC1U10V2KX-1GP  [C402H22]  46.75 135.79 90 bottom
C141  SC1U10V2KX-1GP  [C402H22]  45.32 131.24 270 bottom
C142  SC180P50V2JN-1GP  [C402H22]  45.68 134.87 90 bottom
C143  SC1U10V2KX-1GP  [C402H22]  53.98 142.66 270 bottom
C144  SC1U10V2KX-1GP  [C402H22]  52.2 141.39 0 bottom
C145  SC1U10V2KX-1GP  [C402H22]  53.85 140.88 270 bottom
C146  SC1U10V2KX-1GP  [C402H22]  53.98 141.77 270 bottom
C147  SC1U6D3V2KX-GP  [C402H22]  105.21 80.04 180 top
C148  SCD1U16V2KX-3GP  [C402H22]  132.72 76.68 270 top
C149  SC1U10V2KX-1GP  [C402H22]  132.72 75.67 270 top
C150  SC1U10V2KX-1GP  [C402H22]  89.38 154.66 0 bottom
C151  SC1U10V2KX-1GP  [C402H22]  93.93 154.66 0 bottom
C152  SC10U6D3V3MX-GP  [C603H38]  103 135.76 180 bottom
C153  SC10U6D3V3MX-GP  [C603H38]  87.81 154.58 0 bottom
C154  SC10U6D3V3MX-GP  [C603H38]  87.38 132.12 180 bottom
C155  SC10U6D3V3MX-GP  [C603H38]  99 153.61 0 bottom
C156  SC10U6D3V3MX-GP  [C603H38]  99.67 135.61 180 bottom
C157  SC10U6D3V3MX-GP  [C603H38]  81.86 132.08 180 bottom
C158  SC10U6D3V3MX-GP  [C603H38]  95.43 153.84 0 bottom
C159  SCD1U16V2KX-3GP  [C402H22]  103.12 167.51 180 bottom
C160  SC1U10V2KX-1GP  [C402H22]  104.17 175.57 90 bottom
C161  SC1KP50V2KX-1GP  [C402H22]  104.17 176.51 90 bottom
C173  SCD1U16V2KX-3GP  [C402H22]  104.2 173.63 90 bottom
C174  SC1KP50V2KX-1GP  [C402H22]  104.2 172.74 270 bottom
C175  SC2D2U10V3KX-1GP  [C603H36]  103.96 130.79 90 bottom
C176  SC1KP50V2KX-1GP  [C402H22]  104.28 133.01 270 bottom
C177  SCD47U25V3KX-1GP  [C603H36]  19.96 20.9 0 bottom
C178  SC1U25V3KX-1-GP  [C603H36]  25.1 12.12 180 bottom
C179  SCD1U25V2KX-GP  [C402H22]  28.09 11.79 180 bottom
C180  SCD1U25V2KX-GP  [C402H22]  27.23 11.79 180 bottom
C181  SC4D7U25V5KX-GP  [C805H54]  33.32 19.05 90 bottom
C182  SCD01U50V2KX-1GP  [C402H22]  32.69 14.07 270 bottom
C183  SC100P50V2JN-3GP  [C402H22]  30.72 23.31 0 bottom
C184  SC1U100V6KX-GP  [C1206H71]  40.82 6.96 180 top
C185  SC10U10V5KX-2GP  [C805H54]  119.94 38.58 180 top
C186  SC2D2U10V3KX-1GP  [C603H36]  116.46 38.94 0 top
C187  SCD1U16V2KX-3GP  [C402H22]  122.61 37.85 180 top
C188  SC2D2U10V3KX-1GP  [C603H36]  121.51 38.15 180 top
C189  SC100P50V2JN-3GP  [C402H22]  113.46 36.5 180 top
C190  SC10U10V5KX-2GP  [C805H54]  111 37.19 180 top
C191  SCD1U16V2KX-3GP  [C402H22]  123.49 37.85 0 top
C192  SC10U10V5KX-2GP  [C805H54]  124.97 38.28 180 top
C193  SCD1U16V2KX-3GP  [C402H22]  112.45 36.5 0 top
C194  SC2D2U10V3KX-1GP  [C603H36]  114.17 38.99 270 top
C195  SC10U10V5KX-2GP  [C805H54]  105.31 29.24 0 top
C196  SCD1U16V2KX-3GP  [C402H22]  106.91 29.62 0 top
C197  SC10U10V5KX-2GP  [C805H54]  109.5 33.35 180 top
C198  SCD1U16V2KX-3GP  [C402H22]  111 34.04 180 top
C200  SC10U10V5KX-2GP  [C805H54]  109.63 28.63 0 top
C201  SCD1U16V2KX-3GP  [C402H22]  112.14 28.22 0 top
C205  SC10U10V5KX-2GP  [C805H54]  109.19 24 270 top
C206  SCD1U16V2KX-3GP  [C402H22]  113.41 25.2 0 top
C207  SCD1U16V2KX-3GP  [C402H22]  119.53 24.79 0 top
C208  SC100P50V2JN-3GP  [C402H22]  114.71 25.5 180 top
C209  SC100P50V2JN-3GP  [C402H22]  116.05 25.43 180 top
C211  SC10U25V6KX-1GP  [C1206H71]  72.11 12.62 180 top
C223  SC10U25V6KX-1GP  [C1206H71]  69.82 12.62 180 top
C230  SC1U100V6KX-GP  [C1206H71]  36.37 6.97 180 top
C235  SC1U100V6KX-GP  [C1206H71]  38.6 7.34 0 bottom
C236  SC1U100V6KX-GP  [C1206H71]  36.37 7.34 0 bottom
C237  SC1KP50V2KX-1GP  [C402H22]  109.96 10.97 180 top
C243  SC1KP50V2KX-1GP  [C402H22]  110.01 8.76 0 top
C245  SC1KP50V2KX-1GP  [C402H22]  110.01 4.67 0 top
C246  SC330P100V3JN-GP  [C603H36]  51.41 13.6 0 bottom
C247  SC1KP50V2KX-1GP  [C402H22]  110.01 6.71 180 top
C254  SC2D2U10V3KX-1GP  [C603H36]  124.46 33.12 90 top
C255  SC2D2U10V3KX-1GP  [C603H36]  124.46 34.39 90 top
C256  SC100P50V2JN-3GP  [C402H22]  130.09 31.64 0 top
C257  SC10U6D3V3MX-GP  [C603H38]  129.2 30.07 90 top
C261  SC100P50V2JN-3GP  [C402H22]  132.08 34.67 0 top
C262  SC100P50V2JN-3GP  [C402H22]  132.08 36.7 180 top
C263  SCD1U16V2KX-3GP  [C402H22]  134.59 28.91 180 bottom
C264  SCD1U16V2KX-3GP  [C402H22]  134.47 39.07 180 top
C265  SCD1U16V2KX-3GP  [C402H22]  133.71 28.91 180 bottom
C266  SC1U100V6KX-GP  [C1206H71]  38.6 6.95 180 top
C267  SC2200P50V2KX-2GP  [C402H22]  129.59 38.61 180 top
C268  SCD1U16V2KX-3GP  [C402H22]  113.87 66.55 90 bottom
C269  SCD1U16V2KX-3GP  [C402H22]  105.31 57.15 0 top
C270  SC4D7U6D3V3KX-GP  [C603H36]  121.49 68.71 270 bottom
C271  SCD1U16V2KX-3GP  [C402H22]  121.59 67.67 270 bottom
C272  SCD1U16V2KX-3GP  [C402H22]  112.75 57.94 0 top
C273  SCD1U16V2KX-3GP  [C402H22]  111.56 67.84 90 bottom
C274  SCD1U16V2KX-3GP  [C402H22]  110.13 57.91 0 top
C275  SCD1U16V2KX-3GP  [C402H22]  114.94 57.94 0 top
C276  SCD1U16V2KX-3GP  [C402H22]  105.49 66.29 90 bottom
C277  SCD1U16V2KX-3GP  [C402H22]  105.49 65.41 90 bottom
C278  SC1U10V2KX-1GP  [C402H22]  116.71 58.98 90 top
C279  SCD1U16V2KX-3GP  [C402H22]  111.56 68.76 90 bottom
C280  SCD1U16V2KX-3GP  [C402H22]  116.51 44.86 270 top
C281  SC1KP50V2JN-2GP  [C402H22]  116.56 50.98 90 top
C282  SCD1U16V2KX-3GP  [C402H22]  107.52 62.89 180 top
C283  SCD1U16V2KX-3GP  [C402H22]  106.17 60.58 270 top
C284  SCD1U16V2KX-3GP  [C402H22]  108.03 57.15 0 top
C285  SCD1U16V2KX-3GP  [C402H22]  107.14 57.15 0 top
C286  SCD1U16V2KX-3GP  [C402H22]  116.33 58.5 180 bottom
C287  SCD1U16V2KX-3GP  [C402H22]  108.99 59.97 0 top
C288  SC4D7U6D3V3KX-GP  [C603H36]  102.87 57.02 0 top
C289  SCD1U16V2KX-3GP  [C402H22]  106.22 57.15 0 top
C292  SC1KP2KV6KX-GP  [C1206H71]  128.93 61.98 180 top
C294  SC15P50V2JN-2-GP  [C402H22]  116.66 62.69 0 bottom
C295  SC15P50V2JN-2-GP  [C402H22]  116.66 60.76 180 bottom
C302  SC4D7U6D3V3KX-GP  [C603H36]  114.25 68.35 0 bottom
C303  SCD1U16V2KX-3GP  [C402H22]  131.32 145.97 0 bottom
C304  SCD1U16V2KX-3GP  [C402H22]  133.3 145.97 0 bottom
C305  SCD1U16V2KX-3GP  [C402H22]  134.19 145.97 0 bottom
C306  SC4D7U6D3V3KX-GP  [C603H36]  131.88 143.28 0 bottom
C307  SCD1U50V3KX-GP  [C603H36]  25.1 110.48 0 top
C310  SCD01U50V2KX-1GP  [C402H22]  26.9 72.12 90 top
C311  SCD1U16V2KX-3GP  [C402H22]  61.38 41.84 0 top
C312  SCD1U50V3KX-GP  [C603H36]  20.6 30.96 180 top
C313  SCD01U50V2KX-1GP  [C402H22]  19.95 34.07 270 top
C322  SCD01U50V2KX-1GP  [C402H22]  32.16 17.09 0 bottom
C323  SC1KP50V2JN-2GP  [C402H22]  28.98 11.79 180 bottom
C324  SC1U25V3KX-1-GP  [C603H36]  123.95 27.05 90 top
C325  SC100P50V2JN-3GP  [C402H22]  125.09 25.43 180 top
C326  SC4D7U6D3V3KX-GP  [C603H36]  106.17 60.58 90 bottom
C327  SCD47U16V2ZY-GP  [C402H22]  24.71 47.04 0 top
C328  SCD47U25V3KX-1GP  [C603H36]  60.42 24.07 0 top
C351  SC1U10V2KX-1GP  [C402H22]  67.26 12.12 180 top
C352  SCD1U25V2KX-GP  [C402H22]  68.28 12.14 180 top
C353  SC5P50V2CN-2GP  [C402H22]  14.22 88.37 270 top
C354  SC5P50V2CN-2GP  [C402H22]  14.22 86.84 270 top
C355  SC100P50V2JN-3GP  [C402H22]  24.91 105.11 90 top
C356  SC5P50V2CN-2GP  [C402H22]  14.22 90.78 270 top
C357  SC5P50V2CN-2GP  [C402H22]  14.22 89.26 270 top
C358  SC5P50V2CN-2GP  [C402H22]  14.22 93.19 270 top
C359  SC5P50V2CN-2GP  [C402H22]  14.22 91.67 270 top
C360  SC5P50V2CN-2GP  [C402H22]  14.22 98.02 270 top
C361  SC5P50V2CN-2GP  [C402H22]  14.22 96.44 270 top
C362  SC5P50V2CN-2GP  [C402H22]  14.22 95.55 270 top
C363  SC5P50V2CN-2GP  [C402H22]  14.22 94.08 270 top
C364  SC5P50V2CN-2GP  [C402H22]  14.22 100.46 270 top
C365  SC5P50V2CN-2GP  [C402H22]  14.22 98.91 270 top
C368  SC5P50V2CN-2GP  [C402H22]  14.22 102.84 270 top
C369  SC5P50V2CN-2GP  [C402H22]  14.22 101.35 270 top
C370  SC5P50V2CN-2GP  [C402H22]  14.25 105.23 270 top
C371  SC5P50V2CN-2GP  [C402H22]  14.22 103.73 270 top
C372  SC1U10V2KX-1GP  [C402H22]  12.96 113.3 270 bottom
C373  SC5P50V2CN-2GP  [C402H22]  14.22 109.86 270 top
C374  SC5P50V2CN-2GP  [C402H22]  14.22 108.46 270 top
C375  SCD1U50V3KX-GP  [C603H36]  10.38 107.03 270 bottom
C376  SC5P50V2CN-2GP  [C402H22]  14.22 107.57 270 top
C377  SC5P50V2CN-2GP  [C402H22]  14.25 106.12 270 top
C378  SCD1U16V2KX-3GP  [C402H22]  130.25 128.57 180 bottom
C379  SC1D5P50V2CN-1GP  [C402H22]  130.11 115.25 0 bottom
C380  SCD1U16V2KX-3GP  [C402H22]  129.36 128.57 180 bottom
C381  SCD1U16V2KX-3GP  [C402H22]  127.49 122.77 270 bottom
C382  SCD1U16V2KX-3GP  [C402H22]  127.49 121.7 270 bottom
C383  SCD1U16V2KX-3GP  [C402H22]  127.52 117.64 270 bottom
C384  SC470P50V2JN-GP  [C402H22]  134.42 105.26 180 top
C385  SCD1U16V2KX-3GP  [C402H22]  127.54 118.7 270 bottom
C386  SCD1U16V2KX-3GP  [C402H22]  127.52 114.87 270 bottom
C387  SCD1U16V2KX-3GP  [C402H22]  127.52 113.9 270 bottom
C388  SC1D5P50V2CN-1GP  [C402H22]  130.11 113.32 180 bottom
C389  SCD1U16V2KX-3GP  [C402H22]  136.58 107.85 270 top
C390  SC100P50V2JN-3GP  [C402H22]  134.09 111.56 180 top
C391  SC100P50V2JN-3GP  [C402H22]  134.11 109.58 0 top
C392  SC1D5P50V2CN-1GP  [C402H22]  130.11 119.16 0 bottom
C393  SC1D5P50V2CN-1GP  [C402H22]  130.11 117.18 180 bottom
C394  SC1D5P50V2CN-1GP  [C402H22]  130.11 123.22 0 bottom
C395  SC1D5P50V2CN-1GP  [C402H22]  130.11 121.22 180 bottom
C396  SC1D5P50V2CN-1GP  [C402H22]  130.71 125.98 270 bottom
C397  SC1D5P50V2CN-1GP  [C402H22]  128.73 125.96 90 bottom
C398  SCD1U16V2KX-3GP  [C402H22]  132.72 109.02 90 top
C409  SCD01U50V2KX-1GP  [C402H22]  12.1 147.86 90 bottom
C410  SCD01U50V2KX-1GP  [C402H22]  12.1 148.77 90 bottom
C411  SCD01U50V2KX-1GP  [C402H22]  12.12 151.34 90 bottom
C412  SCD1U16V2KX-3GP  [C402H22]  12.76 165.39 270 bottom
C413  SC10U10V5KX-2GP  [C805H54]  13.19 163.95 270 bottom
C414  SCD01U50V2KX-1GP  [C402H22]  12.14 150.44 90 bottom
C420  SC10U10V5KX-2GP  [C805H54]  8.63 60.41 180 bottom
C421  SC1U25V3KX-1-GP  [C603H36]  10.56 60.52 180 bottom
C422  SCD01U50V2KX-1GP  [C402H22]  12.12 39.6 270 top
C423  SCD01U50V2KX-1GP  [C402H22]  12.12 40.49 270 top
C424  SCD01U50V2KX-1GP  [C402H22]  12.14 42.98 270 top
C425  SCD01U50V2KX-1GP  [C402H22]  12.14 42.09 270 top
C426  SC10U6D3V5KX-1GP  [C805H54]  15.06 71.5 270 bottom
C427  SCD1U16V2KX-3GP  [C402H22]  18.44 71.91 0 top
C428  SC4D7P50V2CN-1GP  [C402H22]  18.74 80.85 90 top
C429  SC4D7P50V2CN-1GP  [C402H22]  22.71 77.52 270 top
C430  SC4D7P50V2CN-1GP  [C402H22]  21.77 76.58 270 top
C431  SCD1U50V3KX-GP  [C603H36]  64.44 57.96 90 top
C432  SCD1U16V2KX-3GP  [C402H22]  88.42 66.12 0 bottom
C433  SCD1U16V2KX-3GP  [C402H22]  123.04 174.98 90 bottom
C434  SCD1U16V2KX-3GP  [C402H22]  123.05 174.08 90 bottom
C435  SC1U25V3KX-1-GP  [C603H36]  85.62 64.34 180 top
C436  SC10U10V5KX-2GP  [C805H54]  86.59 66.12 0 bottom
C441  SCD1U16V2KX-3GP  [C402H22]  82.37 59.74 0 bottom
C444  SCD1U16V2KX-3GP  [C402H22]  121.84 195.92 180 top
C445  SC4D7U6D3V3KX-GP  [C603H36]  122.96 196.03 180 top
C446  SC10U10V5ZY-1GP  [C805H54]  63.13 195.2 0 top
C447  SCD1U16V2KX-3GP  [C402H22]  61.7 195.74 0 top
C450  SC10U10V5KX-2GP  [C805H54]  22.17 55.58 0 top
C451  SCD1U16V2KX-3GP  [C402H22]  21.21 58.39 180 top
C452  SC10P50V2JN-4GP  [C402H22]  74.98 195.36 270 top
C455  SCD1U16V2KX-3GP  [C402H22]  52.1 122.66 0 top
C458  SCD1U16V2KX-3GP  [C402H22]  139.9 81.13 90 top
C460  SC10P50V2JN-4GP  [C402H22]  26.42 33.32 90 top
C467  SC1U10V2KX-1GP  [C402H22]  98.77 194.12 90 top
C468  SCD1U16V2KX-3GP  [C402H22]  63.47 69.7 270 top
C469  SCD1U16V2KX-3GP  [C402H22]  65.46 69.55 90 top
C471  SCD1U16V2KX-3GP  [C402H22]  60.14 72.97 180 top
C472  SCD1U16V2KX-3GP  [C402H22]  61.03 72.97 180 top
C473  SCD1U16V2KX-3GP  [C402H22]  61.95 68.33 180 top
C474  SCD1U16V2KX-3GP  [C402H22]  59.13 68.05 180 top
C475  SCD1U16V2KX-3GP  [C402H22]  58.41 70.5 270 top
C476  SC1U10V2KX-1GP  [C402H22]  56.94 67.52 270 top
C477  SC1U25V3KX-1-GP  [C603H36]  57.32 66.45 270 top
C478  SCD1U16V2KX-3GP  [C402H22]  79.36 67.83 180 top
C479  SC1U10V2KX-1GP  [C402H22]  65.16 72.08 0 top
C480  SCD1U16V2KX-3GP  [C402H22]  66.4 95.96 270 bottom
C481  SC1U10V2KX-1GP  [C402H22]  76.85 63.11 270 bottom
C482  SCD1U16V2KX-3GP  [C402H22]  59.61 87.66 90 top
C483  SCD1U16V2KX-3GP  [C402H22]  74.99 83.28 0 top
C484  SC2D2U10V3KX-1GP  [C603H36]  73.89 83.02 0 top
C485  SCD1U16V2KX-3GP  [C402H22]  74.28 104.59 0 bottom
C486  SC1U25V3KX-1-GP  [C603H36]  75.52 104.86 0 bottom
C487  SCD1U16V2KX-3GP  [C402H22]  75.03 96.19 0 bottom
C488  SC1U25V3KX-1-GP  [C603H36]  79.4 77.55 0 top
C491  SC1U10V2KX-1GP  [C402H22]  71.71 61.62 0 bottom
C493  SCD1U16V2KX-3GP  [C402H22]  53.82 86.11 90 top
C494  SC100P50V2JN-3GP  [C402H22]  64.27 62.42 0 top
C495  SCD1U10V2MX-3GP  [C402H22]  27.43 98.55 90 bottom
C496  SCD1U10V2MX-3GP  [C402H22]  27.43 97.66 90 bottom
C497  SCD1U16V2KX-3GP  [C402H22]  126.88 196.72 180 top
C498  SC10U6D3V3MX-GP  [C603H38]  18.58 106.86 270 top
C499  SCD1U16V2KX-3GP  [C402H22]  23.85 96.47 270 top
C500  SCD1U16V2KX-3GP  [C402H22]  23.85 95.58 270 top
C501  SC10U6D3V3MX-GP  [C603H38]  17.7 88.48 270 top
C502  SCD1U16V2KX-3GP  [C402H22]  18.09 89.73 270 top
C503  SCD1U16V2KX-3GP  [C402H22]  20.83 89.8 90 top
C504  SCD1U16V2KX-3GP  [C402H22]  18.93 90.72 270 top
C505  SCD1U16V2KX-3GP  [C402H22]  20.85 90.73 90 top
C506  SC22U6D3V3MX-1-GP  [C603H40]  20.01 87.29 0 top
C507  SC10U6D3V3MX-GP  [C603H38]  25.73 88.29 180 bottom
C508  SCD1U16V2KX-3GP  [C402H22]  23.07 90.18 0 top
C509  SCD01U50V2KX-1GP  [C402H22]  23.84 94.51 270 top
C510  SCD01U50V2KX-1GP  [C402H22]  21.21 98.93 0 top
C511  SC4D7U6D3V2MX-GP-U  [C402-TO0D2H26]  17.32 87.1 180 bottom
C512  SCD01U50V2KX-1GP  [C402H22]  102.49 3.61 0 top
C679  SCD1U16V2KX-3GP  [C402H22]  41.71 73.84 90 top
C680  SC10P50V2JN-4GP  [C402H22]  25.91 59.77 90 top
C681  SCD1U16V2KX-3GP  [C402H22]  58.41 69.59 270 top
C3601  SC1U10V2KX-1GP  [C402H22]  67.36 26.64 90 top
C3602  SC1U10V2KX-1GP  [C402H22]  67.46 31.86 90 top
C3603  SC1KP50V2KX-L-1-GP  [C402H22]  58.76 30.81 270 top
C3604  SC1KP50V2KX-L-1-GP  [C402H22]  59.7 29.77 270 top
C3605  SCD1U16V2KX-3GP  [C402H22]  59.68 28.88 90 top
C3606  SCD1U16V2KX-3GP  [C402H22]  58.74 32.95 90 top
C3608  SC22U6D3V3MX-1-GP  [C603H40]  67.62 33.9 90 top
C3609  SC22U6D3V3MX-1-GP  [C603H40]  67.44 27.72 90 top
C3614  SC22U6D3V3MX-1-GP  [C603H40]  60.14 27.53 270 top
C3615  SC22U6D3V3MX-1-GP  [C603H40]  58.59 34.14 270 top
C3619  SCD1U50V3KX-GP  [C603H36]  23.8 110.48 0 top
C4801  SCD1U10V2KX-5DLGP  [C402H22]  13.6 113.31 0 top
C5001  SC1U16V3KX-2DLGP  [C603H36]  104.6 122.4 90 bottom
C5002  SC1U16V3KX-2DLGP  [C603H36]  106.49 120.25 180 bottom
C6101  SCD1U25V2KX-2-GP  [C402H22]  39.01 30.01 0 bottom
C6102  SC10U6D3V3MX-GP  [C603H38]  37.82 30.16 0 bottom
C6103  SCD1U25V2KX-2-GP  [C402H22]  31.8 9.61 180 bottom
C6104  SCD1U25V2KX-2-GP  [C402H22]  30.91 9.61 180 bottom
C6510  SC22U6D3V3MX-1-GP  [C603H40]  109.93 49.06 180 bottom
C6511  SC4D7U6D3V3KX-GP  [C603H36]  106.73 51.86 0 bottom
C6512  SCD1U16V2KX-3GP  [C402H22]  104.49 50.92 0 bottom
C6514  SC22U6D3V3MX-1-GP  [C603H40]  132.84 174.5 0 top
C6515  SC22U6D3V3MX-1-GP  [C603H40]  132.84 178.69 180 top
C6516  SC22U6D3V3MX-1-GP  [C603H40]  140 83.49 90 top
C6517  SC22U6D3V3MX-1-GP  [C603H40]  140 82.22 90 top
C6518  SC22U6D3V3MX-1-GP  [C603H40]  133.61 72.5 180 bottom
C6519  SC22U6D3V3MX-1-GP  [C603H40]  132.28 72.49 180 bottom
C6520  SC1U10V2KX-1GP  [C402H22]  11.49 116.84 0 bottom
C6521  SCD1U16V2KX-3GP  [C402H22]  10.37 116.84 0 bottom
C6522  SC4D7U6D3V3KX-GP  [C603H36]  103.38 51.22 0 bottom
C6523  SC100P50V2JN-3GP  [C402H22]  102.79 53.15 270 bottom
C6524  SC22U6D3V3MX-1-GP  [C603H40]  33.71 124.11 90 top
C6525  SC1U10V2KX-1GP  [C402H22]  33.04 130.29 90 top
C6526  SC22U6D3V3MX-1-GP  [C603H40]  32.67 133.41 90 top
C6527  SC1U10V2KX-1GP  [C402H22]  33.95 125.18 90 top
C6528  SC1KP50V2KX-L-1-GP  [C402H22]  38.64 125.84 90 top
C6529  SC1KP50V2KX-L-1-GP  [C402H22]  38.69 126.71 90 top
C6530  SC22U6D3V3MX-1-GP  [C603H40]  37.79 124.81 90 top
C6531  SC22U6D3V3MX-1-GP  [C603H40]  34.32 131.32 270 top
C6532  SCD1U16V2KX-3GP  [C402H22]  34.17 132.36 90 top
C6533  SCD1U16V2KX-3GP  [C402H22]  34.8 123.06 90 top
C6534  SCD1U16V2KX-3GP  [C402H22]  46.61 112.98 270 top
C6535  SCD1U16V2KX-3GP  [C402H22]  54.15 135.89 45 bottom
C6536  SCD1U16V2KX-3GP  [C402H22]  127.81 192.41 180 top
CAM1  ACES-CON8-44-GP  [4260-F08N-00R]  55 198.75 180 top
CMOS1  SW-TACT-4P-60-GP  [SKRBAAE010]  133.91 63.91 0 top
CNVBD2  ACES-CON12-28-GP  [50228-01271-001]  27 5.5 180 top
CPU1  KABINI-GP  [BGA769M24D5H76]  57.5 145 0 top
CRS1  CARDBUS11P-SKT-GP-U  [PSDAT0-09GLBS1ZZ4H1-1]  140.4 145 90 top
D1  BAT54A-7-F-2-GP  [SOT23-2D4-312H48]  46.38 72.19 90 top
D2  BAT54A-7-F-2-GP  [SOT23-2D4-312H48]  45.72 97.7 90 top
D3  BAT54A-7-F-2-GP  [SOT23-2D4-312H48]  42.57 101.72 90 top
D4  BAT54C-7-F-3-GP  [SOT23-2D4-312H48]  133.22 73.03 0 top
D5  BX310F-R1-00000-GP  [D4724AKH44]  43.05 6.78 90 bottom
D7  YSESDA05CT-1-GP  [SOD-523-4H28]  106.32 36.83 0 top
D9  AZ5125-02S-R7G-GP  [SOT23-2D4-312H46]  134.75 31.62 270 top
D12  AZ5125-02S-R7G-GP  [SOT23-2D4-312H46]  134.75 35.69 90 top
D14  1SS355GP-GP  [SOD323AKH40]  132.84 105.79 180 top
D19  SP3010-04UTG-GP  [SLP2510P8-1H22]  131.44 172.48 90 bottom
D20  PJSRV05W-4DW6-GP  [SOT-6H58]  130.01 176.97 90 bottom
D21  AZ5125-02S-R7G-GP  [SOT23-2D4-312H46]  115.77 195.42 270 top
D24  PJSRV05W-4DW6-GP  [SOT-6H58]  133.99 84.33 270 top
D29  P6SBMJ24APT-GP  [D5436AKH97]  133.88 23.57 0 top
DBGH1  JWT-CONN14D-FP3-GP  [A2006WV0-2DX7PSA-6T-P]  107.61 91.41 270 top
DCIN1  DC-JACK200-GP-U  [2DC-G726-Q15]  146.8 18.5 90 top
DIMM1  DDR3-204P-44-GP-U2  [1932207-1-U2]  99 144 270 top
EC1  SC6P50V2CN-1GP  [C402H22]  115.7 57.1 270 bottom
EC2  SC6P50V2CN-1GP  [C402H22]  113.72 57.07 90 bottom
EC3  SC6P50V2CN-1GP  [C402H22]  112.7 57.96 270 bottom
EC4  SC6P50V2CN-1GP  [C402H22]  110.77 57.94 90 bottom
EC5  SC6P50V2CN-1GP  [C402H22]  109.88 56.9 270 bottom
EC6  SC6P50V2CN-1GP  [C402H22]  107.92 56.9 90 bottom
EC7  SC6P50V2CN-1GP  [C402H22]  107.06 57.78 270 bottom
EC8  SC6P50V2CN-1GP  [C402H22]  105.13 57.78 90 bottom
EC9  SCD1U16V2KX-3GP  [C402H22]  135.41 105.26 180 top
EC10  SCD1U16V2KX-3GP  [C402H22]  67.43 32.82 90 top
EC11  SCD1U16V2KX-3GP  [C402H22]  73.28 144.14 0 top
EC12  SCD1U16V2KX-3GP  [C402H22]  84.35 132.11 180 bottom
EC13  SC100P50V2JN-3GP  [C402H22]  9.78 122.05 90 top
EC14  SC100P50V2JN-3GP  [C402H22]  19.74 194.88 90 top
EC15  SC100P50V2JN-3GP  [C402H22]  99.85 52.5 90 top
EC16  SC100P50V2JN-3GP  [C402H22]  93.93 85.24 270 top
EC17  SC100P50V2JN-3GP  [C402H22]  71.09 196.19 180 bottom
EC18  SC100P50V2JN-3GP  [C402H22]  104.88 19.08 180 top
EC302  SC5P50V2CN-2GP  [C402H22]  132.08 147.42 270 bottom
EC326  SC5P50V2CN-2GP  [C402H22]  132.23 155.88 270 bottom
EC327  SC5P50V2CN-2GP  [C402H22]  132.26 152.43 270 bottom
EC328  SC5P50V2CN-2GP  [C402H22]  132.28 139.93 270 bottom
EC329  SC5P50V2CN-2GP  [C402H22]  132.18 137.44 270 bottom
EC330  SC5P50V2CN-2GP  [C402H22]  132.52 133.97 90 bottom
EC701  SC10P50V2JN-L1-GP  [C402H22]  117.47 24.79 0 top
EC702  SC1KP50V2KX-1GP  [C402H22]  121.58 12.82 90 top
EC703  SC1KP50V2KX-1GP  [C402H22]  131.14 10.19 180 top
EC704  SC10P50V2JN-L1-GP  [C402H22]  131.69 30.51 270 top
EC705  SC1KP50V2KX-1GP  [C402H22]  17.07 11.81 270 top
EC706  SC1KP50V2KX-1GP  [C402H22]  18.97 11.81 270 top
EC707  SC1KP50V2KX-1GP  [C402H22]  20.9 11.81 270 top
EC708  SC5P50V2CN-2GP  [C402H22]  132.24 153.98 270 bottom
EC709  SC5P50V2CN-2GP  [C402H22]  131.97 132.27 270 bottom
F1  POLYSW-1D5A24V-GP  [POLYSW-4633-1H63]  74.17 8.03 270 top
F3  POLYSW-1D1A6V-9-GP-U  [POLYSW-2114H30]  137.03 105.56 180 top
F4  POLYSW-2A6V-GP  [POLYSW-3217-UH63]  13.74 159.46 90 bottom
F6  POLYSW-1D1A6V-9-GP-U  [POLYSW-2114H30]  134.24 143.51 90 bottom
F7  POLYSW-2A6V-GP  [POLYSW-3217-UH63]  7.64 64.6 180 bottom
F8  POLYSW-1D1A6V-9-GP-U  [POLYSW-2114H30]  119.57 194.88 270 top
F9  POLYSW-1D1A6V-9-GP-U  [POLYSW-2114H30]  24.31 55.6 180 top
FANC1  ACES-CON3-7-GP  [87212-0312L]  107.3 45.1 0 top
FC1  SC33P50V2JN-3GP  [C402H22]  130.72 104.34 270 top
FC2  SC56P50V2JN-2GP  [C402H20]  76.05 150.67 0 bottom
FC3  SCD01U25V2KX-3GP  [C402H22]  73.13 133.6 180 bottom
FC4  SC33P50V2JN-3GP  [C402H22]  55.52 19.33 270 top
G1  COPPER-CLOSE-GP-U  [CON2C-U]  70.51 66.93 270 top
G2  COPPER-CLOSE-GP-U  [CON2C-U]  136.14 6.02 0 top
G3  GAP-OPEN  [CON2O-U]  135.53 64.54 180 top
GDT1  P4500SCLHLRP-GP  [TVS5436-1121H105]  128.27 61.85 180 bottom
H1  GENS315R158-8-F-A-GP  [GENS315R158-8-F-A]  137 195 180 top
H2  GENS315R158-8-F-A-GP  [GENS315R158-8-F-A]  9 195 180 top
H3  GENS315R158-8-F-A-GP  [GENS315R158-8-F-A]  5 5 180 top
H4  GENS315R158-8-F-A-GP  [GENS315R158-8-F-A]  145 5 180 top
H5  GENS315R158-8-F-A-GP  [GENS315R158-8-F-A]  125 95 180 top
HDD1  SKT-SATA7P-15P-163-GP  [C166KK-12209-L]  5.7 162.3 270 top
HDMI1  SKT-HDMI23-47-GP  [SKT-HDMI23-150122-9]  141.5 117.5 90 top
HDT1  DM-SMC-CONN20A-1-GP-01  [DM-ASP-137098-05-01]  88 193.5 0 top
HS1  STF237R128H34-4-GP  [STF237R128H34]  90 145 180 top
HS2  STF237R128H34-4-GP  [STF237R128H34]  25 145 180 top
HS3  STF256R109H124-GP  [STF256R109H124]  5.25 20.75 180 top
HS4  STFT256B126R113H62-1-GP  [STFT256B126R113H62]  37.3 40.2 180 top
HS5  STFT256B126R113H62-1-GP  [STFT256B126R113H62]  96.8 94 180 top
L1  HCB2012KF-420T40-GP  [L805H42]  34.32 145.49 90 bottom
L3  MHC1608S601LBP-GP  [L603H38]  108.64 35.92 270 top
L4  FCM1608KFG-301T05-GP  [L1608-UH38]  107.04 32.28 90 top
L5  MHC1608S601LBP-GP  [L603H38]  109.58 25.6 90 top
L7  PBY160808T-471Y-N-GP  [L1608-UH38]  108.85 11.24 0 top
L9  PBY160808T-471Y-N-GP  [L1608-UH38]  108.21 9.27 90 top
L11  PBY160808T-471Y-N-GP  [L1608-UH38]  107.95 5.11 90 top
L13  PBY160808T-471Y-N-GP  [L1608-UH38]  107.95 6.5 90 top
L18  0R0603-PAD-2-GP-U  [0R0603-PAD-1-U]  129.36 33.26 90 top
L19  FCM1608KFG-301T05-GP  [L1608-UH38]  129.92 35.13 90 top
L20  FCM1608KFG-301T05-GP  [L1608-UH38]  129.92 36.32 90 top
L21  IND-4D7UH-210-GP  [L3330-1230H95]  117.23 67.7 270 bottom
L22  COIL-90OHM-100MHZ-5-GP  [L125100-4P-4H24]  132.6 46.29 180 top
L23  COIL-90OHM-100MHZ-5-GP  [L125100-4P-4H24]  132.58 52.23 180 top
L24  COIL-90OHM-100MHZ-5-GP  [L125100-4P-4H24]  132.56 49.24 180 top
L25  COIL-90OHM-100MHZ-5-GP  [L125100-4P-4H24]  132.57 55.18 180 top
L27  IND-22UH-147-GP  [L120120-5022-2H237]  59.61 10.79 270 top
L38  MHC1608S800QBP-GP  [L603H38]  10.49 114.43 0 bottom
L40  COIL-90OHM-100MHZ-5-GP  [L125100-4P-4H24]  125.95 176.09 180 bottom
L41  COIL-90OHM-100MHZ-5-GP  [L125100-4P-4H24]  78.34 195.18 270 top
L44  COIL-90OHM-100MHZ-5-GP  [L125100-4P-4H24]  23.01 60.55 0 top
L47  COIL-90OHM-100MHZ-5-GP  [L125100-4P-4H24]  129.92 83.06 180 top
L49  COIL-90OHM-100MHZ-5-GP  [L125100-4P-4H24]  41.78 32.84 90 top
L50  MHC1608S601LBP-GP  [L603H38]  64.58 65.7 90 top
L51  MHC1608S600QBP-GP  [L603H38]  26.7 89.1 180 top
L52  COIL-4D7UH-21-GP  [L3030-3009H40]  22.51 88.21 270 bottom
L53  MHC1608S600QBP-GP  [L603H38]  22.52 86.76 270 top
L54  MHC1608S601LBP-GP  [L603H38]  130.18 12.19 90 top
L55  MHC1608S601LBP-GP  [L603H38]  131.09 7.19 270 top
L56  MHC1608S601LBP-GP  [L603H38]  119.25 12.8 270 top
L72  COIL-90OHM-100MHZ-5-GP  [L125100-4P-4H24]  129.92 85.22 180 top
L74  MHC1608S601LBP-GP  [L603H38]  69.05 194.33 90 top
L75  MHC1608S601LBP-GP  [L603H38]  69.04 195.57 90 top
L2901  MCM1012B900FBP-GP-U  [L125100-4P-1H37]  27.38 66 270 bottom
LAN1  RTL8111G-CGT-1-GP-U2  [QFN32J4-G2D85H36]  112.09 62.43 0 bottom
LVDS19  PTWO-CON30-3-GP-U  [196108-30041-U]  8.5 102 270 top
NGFFE1  SKT-NGFF75P-91-GP  [AS0BC21-S40BE-7H]  33.5 20.75 270 top
NOREF  *  [unnamed]  -0.64 191.13 0 top
NOREF#2  -  [#2]  47.32 30.94 0 top
NOREF#3  -  [#2]  0 0 0 top
NOREF#4  -  [#2]  46.38 37.11 0 top
NOREF#5  -  [#2]  -99.64 -10.05 0 top
NOREF#6  *  [unnamed]  133.31 42.71 0 top
NOREF#7  -  [#2]  0 0 0 top
NOREF#8  -  [#2]  14.73 24.51 0 top
NOREF#9  *  [unnamed]  90.16 112.17 0 top
NOREF#10  *  [unnamed]  144.6 194.16 0 top
NOREF#11  -  [unnamed]  -1.48 196.44 0 top
NOREF#12  *  [unnamed]  23.07 172.16 0 top
NOREF#13  -  [#2]  88.65 7.47 0 top
NOREF#14  -  [#2]  19.26 -633.55 0 top
NOREF#15  -  [unnamed]  153.83 189.25 0 top
NOREF#16  -  [unnamed]  -3.91 5.75 0 top
NOREF#17  -  [unnamed]  153.95 6 0 top
NOREF#18  *  [unnamed]  4.95 13.64 0 top
NOREF#19  *  [unnamed]  102.24 20.83 0 top
NOREF#20  -  [#2]  157.8 122.81 0 top
NOREF#21  -  [#2]  99.42 187.17 0 top
NOREF#22  *  [unnamed]  139.45 10.08 0 top
NOREF#23  *  [unnamed]  144.6 194.16 180 bottom
NOREF#24  *  [unnamed]  41.68 65.81 180 bottom
NOREF#25  *  [unnamed]  -0.64 191.13 180 bottom
NOREF#26  *  [unnamed]  4.95 13.64 180 bottom
NOREF#27  *  [unnamed]  88.93 89.98 180 bottom
NOREF#28  *  [unnamed]  139.45 10.08 180 bottom
ODD1  SKT-SATA7P-206-GP  [WATA-07APLDJ6U]  6.65 40.5 90 top
ODDPW1  CLX-CON2-7-GP  [CI0102M1HR0-LF]  4.5 61 90 top
PC1  SC100P50V2JN-3GP  [C402H22]  127.28 8.46 0 bottom
PC2  SCD1U50V3KX-GP  [C603H36]  128.98 23.06 0 top
PC3  SC1U50V5ZY-1-GP-U  [C805H58]  130.53 23.42 180 top
PC4  SCD1U25V2KX-GP  [C402H22]  125.72 23.47 90 top
PC6  SCD1U16V2KX-3GP  [C402H22]  127.56 4.67 270 bottom
PC7  SCD1U50V3KX-GP  [C603H36]  106.98 18.77 180 top
PC8  SC1U50V5ZY-1-GP-U  [C805H58]  121.03 21.01 180 top
PC4205  SCD1U16V2KX-3GP  [C402H22]  127.96 5.85 90 bottom
PC4401  SC1KP50V2KX-1GP  [C402H22]  32.28 187.05 180 bottom
PC4402  SC330P50V2JN-1-DL-GP  [C402H22]  27.64 183.28 90 top
PC4403  SC680P50V2KX-2GP  [C402H22]  26.74 189.01 270 top
PC4404  SC47P50V2JN-3GP  [C402H22]  30.08 187.66 0 top
PC4405  SC1KP50V2JN-2GP  [C402H22]  26.76 185.03 90 top
PC4406  SCD01U16V2KX-3LLGP  [C402H22]  27.64 182.18 270 top
PC4407  SCD1U25V2KX-GP  [C402H22]  11.66 186.82 270 top
PC4408  SC10U25V5KX-GP  [C805H56]  18.82 186.49 90 top
PC4409  SC10U25V5KX-GP  [C805H56]  18.8 184.48 90 top
PC4410  SCD056U16V2KX-GP  [C402H22]  31.14 182.53 270 top
PC4411  SCD1U10V2KX-4-LL-GP  [C402H22]  31.14 181.59 270 top
PC4412  SC150P50V2KX-GP  [C402H22]  28.68 188.18 270 top
PC4413  SC330P50V2JC-2-GP  [C402H22]  29.75 183.1 180 top
PC4414  SCD01U50V2KX-1GP  [C402H22]  27.62 184.16 90 top
PC4415  SCD1U50V3KX-GP  [C603H36]  27.97 192.42 90 top
PC4416  SC470P50V2KX-3GP  [C402H22]  29.97 179.72 90 top
PC4417  SC1KP50V2KX-1GP  [C402H22]  20.44 176.66 180 bottom
PC4418  SC10U6D3V3MX-GP  [C603H38]  24.89 165.46 90 top
PC4419  SC10U6D3V3MX-GP  [C603H38]  24.89 166.65 90 top
PC4420  SC10U6D3V3MX-GP  [C603H38]  24.89 167.85 90 top
PC4421  SC1U10V2KX-1GP  [C402H22]  31.76 194.07 270 top
PC4422  SC1U10V2KX-1GP  [C402H22]  33.74 194.07 90 top
PC4423  SC1U10V2KX-1GP  [C402H22]  35.42 183.69 180 top
PC4424  SC1KP50V2KX-1GP  [C402H22]  34.2 187.04 0 bottom
PC4425  SCD1U50V3KX-GP  [C603H36]  64.34 193.8 90 bottom
PC4426  SC10U25V6KX-1GP  [C1206H71]  72.97 192.66 270 bottom
PC4427  SC10U25V6KX-1GP  [C1206H71]  72.95 188.14 270 bottom
PC4428  SC10U25V6KX-1GP  [C1206H71]  72.95 185.93 270 bottom
PC4429  SCD1U16V2KX-3GP  [C402H22]  35.15 191.47 180 bottom
PC4430  SCD22U10V2KX-2-GP  [C402H22]  40.4 185.27 90 top
PC4431  SCD1U50V3KX-GP  [C603H36]  35.18 194.31 180 bottom
PC4432  SCD01U50V2KX-1GP  [C402H22]  40.03 191.06 0 bottom
PC4433  SCD1U16V2KX-3GP  [C402H22]  45.65 183.34 0 top
PC4434  SC1KP50V2KX-1GP  [C402H22]  47.89 190.61 90 bottom
PC4435  SC47P50V2JN-3GP  [C402H22]  39.23 191.2 0 top
PC4436  SC100P50V2JN-3GP  [C402H22]  40.22 188.94 0 top
PC4437  SC470P50V2KX-3-LL-GP  [C402H22]  36.62 188.77 90 bottom
PC4438  SC470P50V2KX-3-LL-GP  [C402H22]  44.36 186.84 270 top
PC4439  SCD22U10V2KX-1GP  [C402H22]  42.79 185.44 180 top
PC4440  SCD1U10V2KX-4DLGP  [C402H22]  41.82 185.45 180 top
PC4441  SC330P50V2KX-3GP  [C402H22]  40.69 192.02 90 top
PC4442  SC680P50V2KX-2GP  [C402H22]  44.26 191.14 180 top
PC4443  SC10U25V5KX-GP  [C805H56]  11.68 185.36 270 top
PC4445  SC10U25V6KX-1GP  [C1206H71]  72.95 190.36 270 bottom
PC4801  SC1KP50V2KX-1DLGP  [C402H22]  15.34 144.23 180 top
PC4803  SC10U25V6KX-1GP  [C1206H71]  14.04 124.9 180 bottom
PC4804  SCD1U50V3KX-GP  [C603H36]  11.96 125.48 0 top
PC4805  SCD1U50V3KX-GP  [C603H36]  17.15 119.29 180 top
PC4806  SC1U10V2KX-1GP  [C402H22]  18.17 117.86 180 top
PC4807  SC1KP50V2KX-1GP  [C402H22]  19.2 130.17 0 bottom
PC4808  SC22U6D3V3MX-1-GP  [C603H40]  27.93 128.18 180 top
PC4809  SCD1U16V2KX-3GP  [C402H22]  29.04 127.83 180 top
PC4810  SC18P50V2JN-1DLGP  [C402H22]  20.42 111.29 0 top
PC4901  SCD01U50V2KX-1GP  [C402H22]  96.68 15.7 0 top
PC4902  SC10U25V6KX-1GP  [C1206H71]  98.52 15.74 180 bottom
PC4903  SC10U25V6KX-1GP  [C1206H71]  98.51 15.74 0 top
PC4905  SCD1U50V3KX-GP  [C603H36]  80.88 27.12 0 top
PC4906  SC1U6D3V2KX-GP  [C402H22]  80.68 32.92 90 top
PC4907  SC10U25V6KX-1GP  [C1206H71]  93 23.81 90 bottom
PC4908  SCD01U50V2KX-1GP  [C402H22]  93.65 22.1 90 bottom
PC4909  SCD1U50V3KX-GP  [C603H36]  78.31 26.59 0 top
PC4911  SC1U6D3V2KX-GP  [C402H22]  69.44 16.82 270 top
PC4912  SC1KP50V2KX-1GP  [C402H22]  87.31 28.94 0 top
PC4913  SC1KP50V2KX-1GP  [C402H22]  87.77 11.38 270 top
